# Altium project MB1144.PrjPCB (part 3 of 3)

## Sheet IDD_measurement.SchDoc: IDD_measurement
size A3; DocumentNumber: 7; Revision: C-02; SheetNumber: 7; SheetTotal: 26; Project: STM32L476G-EVAL
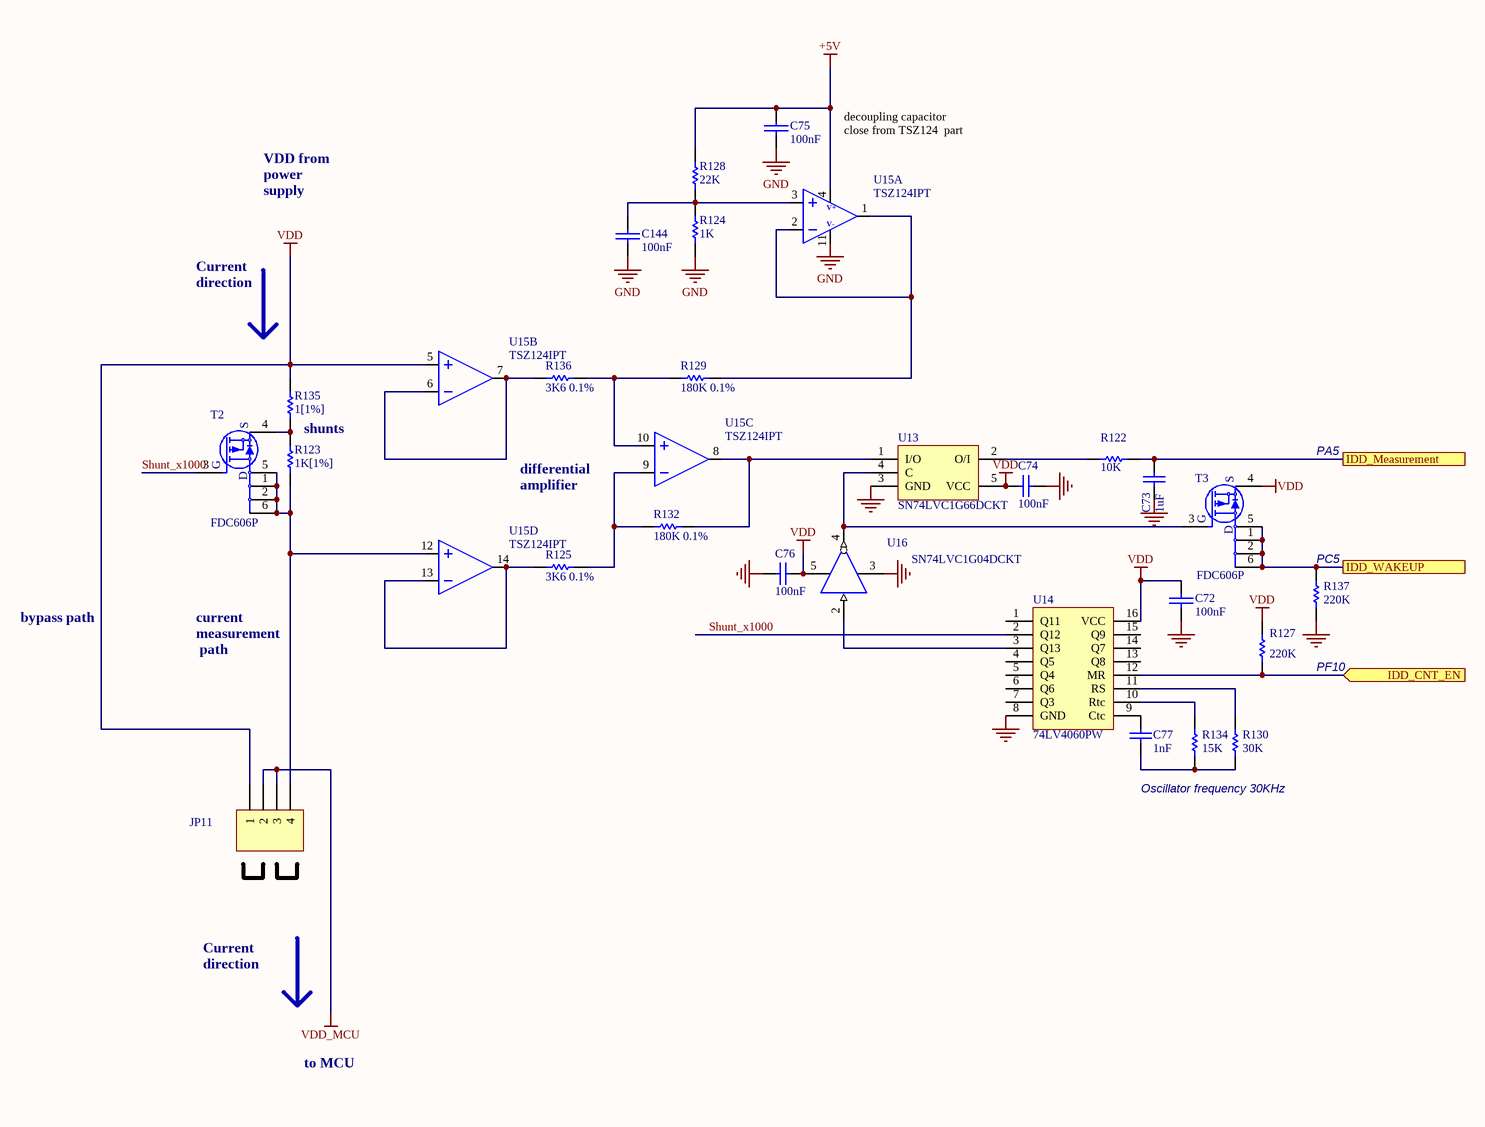
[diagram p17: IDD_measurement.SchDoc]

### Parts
C72  100nF  [0402C]
C73  1uF  [0603C]
C74  100nF  [0402C]
C75  100nF  [0402C]
C76  100nF  [0402C]
C77  1nF  [0402C]
C144  100nF  [0402C]
JP11  Header 4  [SIP4]  (value not drawn)
R122  10K  [0402R]
R123  1K[1%]  [0603R]
R124  1K  [0402R]
R125  3K6 0.1%  [0402R]
R127  220K  [0402R]
R128  22K  [0402R]
R129  180K 0.1%  [0402R]
R130  30K  [0402R]
R132  180K 0.1%  [0402R]
R134  15K  [0402R]
R135  1[1%]  [0603R]
R136  3K6 0.1%  [0402R]
R137  220K  [0402R]
T2  FDC606P  [SOT23-6]
T3  FDC606P  [SOT23-6]
U13  SN74LVC1G66DCKT  [SC70-5]
U14  74LV4060PW  [TSSOP16_0R65_5x6R4]
U15  TSZ124IPT  [TSSOP14_0R65_5X6R4]  (parts A,B,C,D of 4)
U16  SN74LVC1G04DCKT  [SC70-5]

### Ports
IDD_CNT_EN (in), IDD_Measurement, IDD_WAKEUP

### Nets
+5V: C75.1 R128.1 U15.4
GND: C72.2 C73.2 C74.1 C75.2 C76.2 C144.2 R124.2 R137.2 U13.3(GND) U14.8(GND) U15.11 U16.3(GND)
VDD: C72.1 C74.2 C76.1 JP11.1 R127.1 R135.2 T3.4(S) U13.5(VCC) U14.16(VCC) U15.5 U16.5(VCC)
VDD_MCU: JP11.2 JP11.3
Shunt_x1000: T2.3(G) U14.2(Q12)
NetC73_1: C73.1 R122.2 ; port IDD_Measurement
NetC77_1: C77.1 U14.9(Ctc)
NetC77_2: C77.2 R130.2 R134.2
NetC144_1: C144.1 R124.1 R128.2 U15.3
NetJP11_4: JP11.4 R123.1 T2.1(D) T2.2(D) T2.5(D) T2.6(D) U15.12
NetR91_1: R127.2 U14.12(MR) ; port IDD_CNT_EN
NetR122_1: R122.1 U13.2(O/I)
NetR123_2: R123.2 R135.1 T2.4(S)
NetR125_1: R125.1 U15.13 U15.14
NetR125_2: R125.2 R132.1 U15.9
NetR129_1: R129.1 R136.2 U15.10
NetR129_2: R129.2 U15.1 U15.2
NetR130_1: R130.1 U14.11(RS)
NetR132_2: R132.2 U13.1(I/O) U15.8
NetR134_1: R134.1 U14.10(Rtc)
NetR136_1: R136.1 U15.6 U15.7
NetR137_1: R137.1 T3.1(D) T3.2(D) T3.5(D) T3.6(D) ; port IDD_WAKEUP
NetT3_3: T3.3(G) U13.4(C) U16.4(1Y)
NetU14_3: U14.3(Q13) U16.2(1A)

Not connected (* = marked no-connect by the designer): U14 1(Q11) 4(Q5) 5(Q4) 6(Q6) 7(Q3) 13(Q8) 14(Q7) 15(Q9); U16 1(NC)

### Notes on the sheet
- decoupling capacitor
  close from TSZ124  part
- VDD from power supply
- Current direction
- shunts
- PA5
- differential
  amplifier
- (near R137) PC5
- bypass path
- current
  measurement
  path
- PF10
- Oscillator frequency 30KHz
- to MCU

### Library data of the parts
C72 C75 C144 = CAP: Ordered by: Subcon; ECCN_US/EU: NA
C73 = CAP: Capacitor; Value: 100nF; Ordered by: Subcon; ECCN_US/EU: NA
C74 C76 = CAP: Capacitor; Value: 100pF; Ordered by: Subcon; ECCN_US/EU: NA
C77 = Cap: Capacitor; Value: 10nF; Ordered by: Subcon; ECCN_US/EU: NA
JP11 = Header 4: Header, 4-Pin; Ordered by: Subcon
R122 R123 R125 R127-R130 R132 R134-R137 = res1: Resistor; Value: 1K; Ordered by: Subcon; ECCN_US/EU: NA
R124 = res1: Resistor; Ordered by: Subcon; ECCN_US/EU: NA
T2 T3 = STT5PF20V: Manuf_1: Fairchild; Ordered by: Subcon; ECCN_US/EU: EAR99/NEC
U13 = 74H1G66STR: Manuf_1: TI; Ordered by: Subcon; ECCN_US/EU: EAR99/NEC
U14 = M74HC4060TTR: Manuf_1: NXP; Ordered by: Subcon; ECCN_US/EU: EAR99/NEC
U15 = AOP-14PINS: Very high accuracy (5 µV) zero drift 5 V quad OpAmp; Ordered by: ST; ECCN_US/EU: EAR99/NEC; Ref St: 9177442
U16 = 74LX1G04CTR: Manuf_1: TI; Ordered by: Subcon; ECCN_US/EU: EAR99/NEC

## Sheet USB_OTG_FS.SchDoc: USB_OTG_FS
size A4; DocumentNumber: 23; Revision: C-02; SheetNumber: 23; SheetTotal: 26; Project: STM32L476G-EVAL
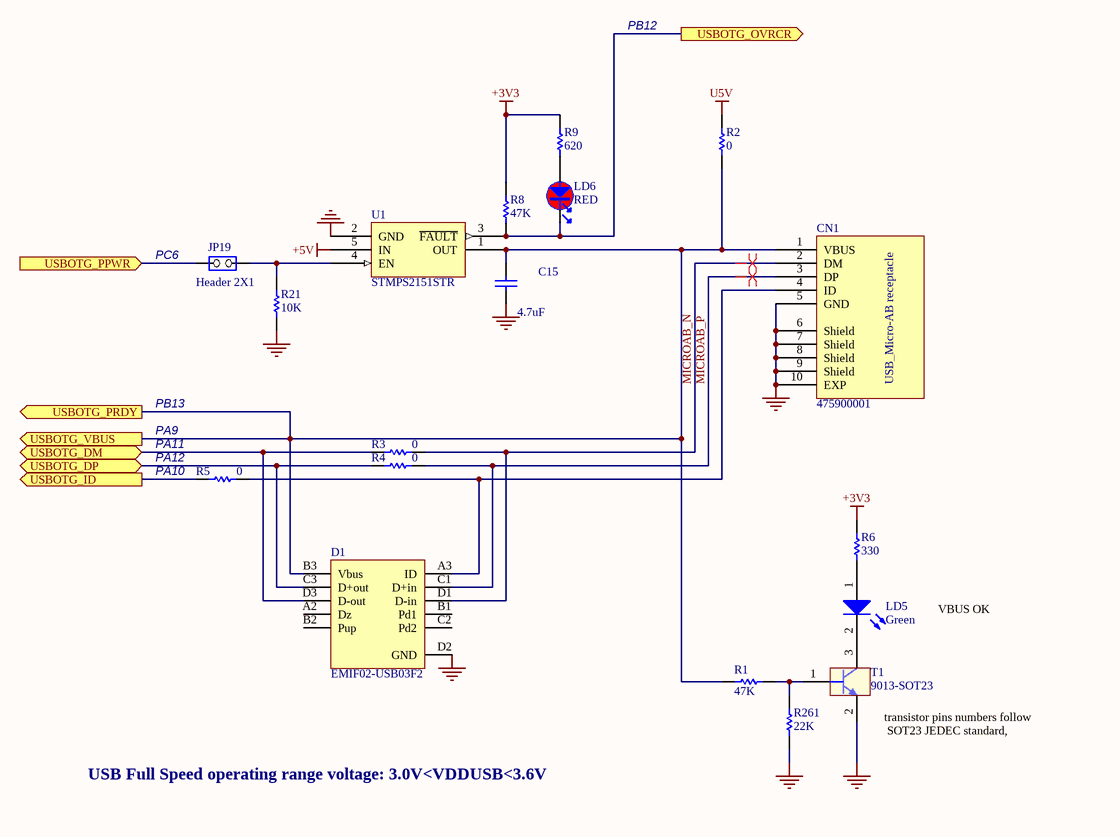
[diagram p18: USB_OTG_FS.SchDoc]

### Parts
C15  4.7uF  [0603C]
CN1  475900001  [MOLEX_47590001]
D1  EMIF02-USB03F2  [BGA11_0R5_1R57X2R07]
JP19  Header 2X1  [SIP2]
LD5  Green  [0603D]
LD6  value RED  [LED_0603_RED_H0P4]  (hidden comment: LED_red)
R1  47K  [0402R]
R2  0  [0603R]
R3  0  [0603R]
R4  0  [0603R]
R5  0  [0603R]
R6  330  [0402R]
R8  47K  [0402R]
R9  620  [0402R]
R21  10K  [0402R]
R261  22K  [0402R]
T1  9013-SOT23  [SOT-23]
U1  STMPS2151STR  [SOT23-5]

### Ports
USBOTG_DM (bidir), USBOTG_DP (bidir), USBOTG_ID (out), USBOTG_OVRCR (out), USBOTG_PPWR (in), USBOTG_PRDY (out), USBOTG_VBUS (out)

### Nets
+3V3: R6.1 R8.1 R9.1
+5V: U1.5(IN)
GND: C15.2 CN1.5(GND) CN1.6(Shield) CN1.7(Shield) CN1.8(Shield) CN1.9(Shield) CN1.10(EXP) D1.D2(GND) R21.1 R261.1 T1.2(E) U1.2(GND)
U5V: R2.1
MICROAB_N: CN1.2(DM) D1.D1(D-in) R3.1
MICROAB_P: CN1.3(DP) D1.C1(D+in) R4.1
PA11: D1.D3(D-out) R3.2 ; port USBOTG_DM
PA12: D1.C3(D+out) R4.2 ; port USBOTG_DP
NetC15_1: C15.1 CN1.1(VBUS) D1.B3(Vbus) R1.1 R2.2 U1.1(OUT) ; port USBOTG_VBUS, port USBOTG_PRDY
NetCN1_4: CN1.4(ID) D1.A3(ID) R5.1
NetCN11_6: R5.2 ; port USBOTG_ID
NetJP19_1: JP19.1(COMMON) ; port USBOTG_PPWR
NetJP19_2: JP19.2(NO) R21.2 U1.4(EN)
NetLD5_1: LD5.1(A) R6.2
NetLD5_2: LD5.2(K) T1.3(C)
NetLD6_1: LD6.1 R9.2
NetLD6_2: LD6.2 R8.2 U1.3(~{FAULT}) ; port USBOTG_OVRCR
NetR1_2: R1.2 R261.2 T1.1(B)

Not connected (* = marked no-connect by the designer): D1 A2(Dz) B1(Pd1) B2(Pup) C2(Pd2)

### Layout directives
differential pair: MICROAB_N, MICROAB_P

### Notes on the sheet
- PB12
- (near JP19) PC6
- PA9
- PB13
- (near R5) PA10
- (near R5) PA11
- (near R5) PA12
- VBUS OK
- (near T1) transistor pins numbers follow
  SOT23 JEDEC standard,
- USB Full Speed operating range voltage: 3.0V<VDDUSB<3.6V

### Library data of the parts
C15 = CAP: as C73 on sheet IDD_measurement
CN1 = 475900001: Ordered by: Subcon; ECCN_US/EU: NA; Comments: USB Micro AB receptacle
D1 = EMIF02-USB03F2: Ordered by: ST; ECCN_US/EU: EAR99/NEC; Ref St: 9179037
JP19 = JP2: Ordered by: Subcon; ECCN_US/EU: NA
LD5 = LED2: Typical RED, GREEN, YELLOW, AMBER GaAs LED; Ordered by: Subcon; ECCN_US/EU: NA
LD6 = MCD-02787: LED, Red, VF : Min=1.7V , Max=2.2V, IF : 25mA, 0603 SMD; Part_Type: Display; Part_Preference: Alternate; Manufacturer: EVERLIGHT; Manufacturer_Part_Number: 19-217/R6C-AL1M2VY/6T; Partial_Alternate_Internal_Part_Number: MCD-02401; Component_Country_Of_Origin: China; Alternate_EMS: A; ShowFields: YES; ID: 4899
R1 R6 R8 R9 R261 = res1: as R122 on sheet IDD_measurement
R2-R5 R21 = Res1: Resistor; Value: 1K; Ordered by: Subcon; ECCN_US/EU: NA
T1 = 9013-SOT23: NPN Bipolar Transistor; Manuf_1: Taitron; Manuf_Part_1: MMBT9013; Ordered by: Subcon; ECCN_US/EU: EAR99/NEC
U1 = STMPS2141STR: Ordered by: ST; ECCN_US/EU: EAR99/NEC; Ref St: 9159009

## Sheet Touch Sensing.SchDoc: Touch Sensing
size A4; DocumentNumber: 13; Revision: C-02; SheetNumber: 13; SheetTotal: 26; Project: STM32L476G-EVAL
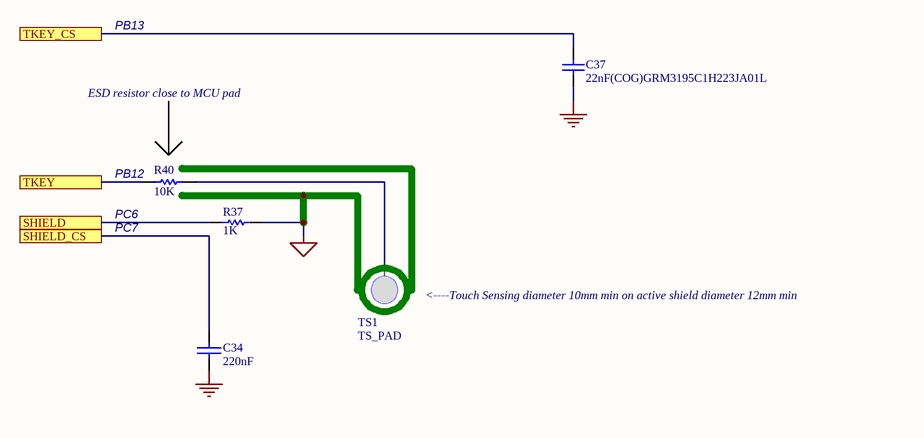
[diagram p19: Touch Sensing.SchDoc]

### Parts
C34  220nF  [0603C]
C37  22nF(COG)GRM3195C1H223JA01L  [1206C]
R37  1K  [0402R]
R40  10K  [0402R]
TS1  TS_PAD  [TS_PAD]

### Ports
SHIELD, SHIELD_CS, TKEY, TKEY_CS

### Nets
GND: C34.1 C37.1
TS_SHIELD: R37.2
NetC34_2: C34.2 ; port SHIELD_CS
NetC37_2: C37.2 ; port TKEY_CS
NetR37_1: R37.1 ; port SHIELD
NetR39_1: R40.1 ; port TKEY
NetR40_2: R40.2 TS1.1

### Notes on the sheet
- PB13
- ESD resistor close to MCU pad
- (near R40) PB12
- (near R40) PC6
- (near R40) PC7
- (near TS1) <----Touch Sensing diameter 10mm min on active shield diameter 12mm min

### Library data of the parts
C34 = CAP: Capacitor; Ordered by: Subcon; ECCN_US/EU: NA
C37 = CAP: as C74 on sheet IDD_measurement
R37 = Res1: Resistor; Ordered by: Subcon; ECCN_US/EU: NA
R40 = Res1: as R2-R5 on sheet USB_OTG_FS
TS1 = TS_PAD: Ordered by: Subcon; ECCN_US/EU: NA; Assembly: with transparent plastic cover; Comments: touch sensing button

## Sheet CAN.SchDoc: CAN
size A4; DocumentNumber: 26; Revision: C-02; SheetNumber: 26; SheetTotal: 26; Project: STM32L476G-EVAL
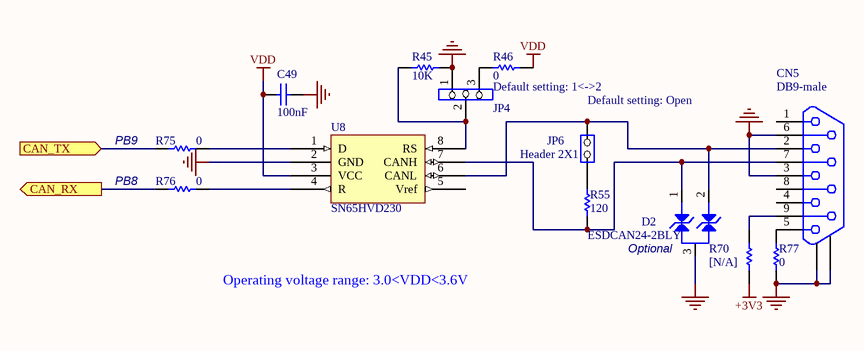
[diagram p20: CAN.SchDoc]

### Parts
C49  100nF  [0402C]
CN5  DB9-male  [DB9/M]
D2  ESDCAN24-2BLY  [SOT23-213]
JP4  Header 3X1  [SIP3]  (value not drawn)
JP6  Header 2X1  [SIP2]
R45  10K  [0402R]
R46  0  [0603R]
R55  120  [0402R]
R70  [N/A]  [0603R]
R75  0  [0603R]
R76  0  [0603R]
R77  0  [0603R]
U8  SN65HVD230  [SOIC8_1R27_4R9X6]

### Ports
CAN_RX (out), CAN_TX (in)

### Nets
+3V3: R70.1
GND: C49.1 CN5.3 CN5.6 CN5.10 CN5.11 D2.3 JP4.1 R45.2 R77.1 U8.2(GND)
VDD: C49.2 R46.2 U8.3(VCC)
NetCN5_2: CN5.2 D2.2 JP6.2(NO) U8.6(CANL)
NetCN5_5: CN5.5 R77.2
NetCN5_7: CN5.7 D2.1 R55.1 U8.7(CANH)
NetCN5_9: CN5.9 R70.2
NetCN11_8: R75.2 ; port CAN_TX
NetCN11_24: R76.1 ; port CAN_RX
NetJP4_2: JP4.2 R45.1 U8.8(RS)
NetJP4_3: JP4.3 R46.1
NetJP6_1: JP6.1(COMMON) R55.2
NetR75_1: R75.1 U8.1(D)
NetR76_2: R76.2 U8.4(R)

Not connected (* = marked no-connect by the designer): CN5 1 4 8; U8 5(Vref)

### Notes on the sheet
- Default setting: 1<->2
- (near JP6) Default setting: Open
- PB9
- PB8
- (near D2) Optional
- Operating voltage range: 3.0<VDD<3.6V

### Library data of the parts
C49 = CAP: as C34 on sheet Touch Sensing
CN5 = DB9: Ordered by: Subcon; Comments: DB9 CAN; ECCN_US/EU: NA
D2 = ESDCAN24-2BLY: Ordered by: ST; ECCN_US/EU: EAR99/NEC; Ref St: 9179002
JP4 = Jumper3: Ordered by: Subcon; ECCN_US/EU: NA
JP6 = JP2: Ordered by: Subcon; ECCN_US/EU: NA
R45 R46 R55 R77 = res1: as R122 on sheet IDD_measurement
R70 = res1: Resistor; Value: 1K; Ordered by: Subcon; ECCN_US/EU: NA; Fitted: NO
R75 R76 = Res1: as R2-R5 on sheet USB_OTG_FS
U8 = SN65HVD230D: Manuf_1: TI; Ordered by: Subcon; ECCN_US/EU: EAR99/NEC; Comments: QSPI memory

## Sheet peripherals.SchDoc: peripherals
size A4; DocumentNumber: 25; Revision: C-02; SheetNumber: 25; SheetTotal: 26; PageSetup: Record=PageOptions¦CenterHorizontal=True¦CenterVertical=True¦PrintScale=1.39¦XCorrection=1.00¦YCorrection=1.00¦PrintKind=1¦BorderSize=5000000¦LeftOffset=0¦BottomOffset=0¦Orientation=2¦PaperLength=1000¦PaperWidth=1000¦Scale=100¦PaperSource=264¦PrintQuality=600¦MediaType=1¦DitherType=10¦PaperKind=A3¦PrintScaleMode=1; Project: STM32L476G-EVAL
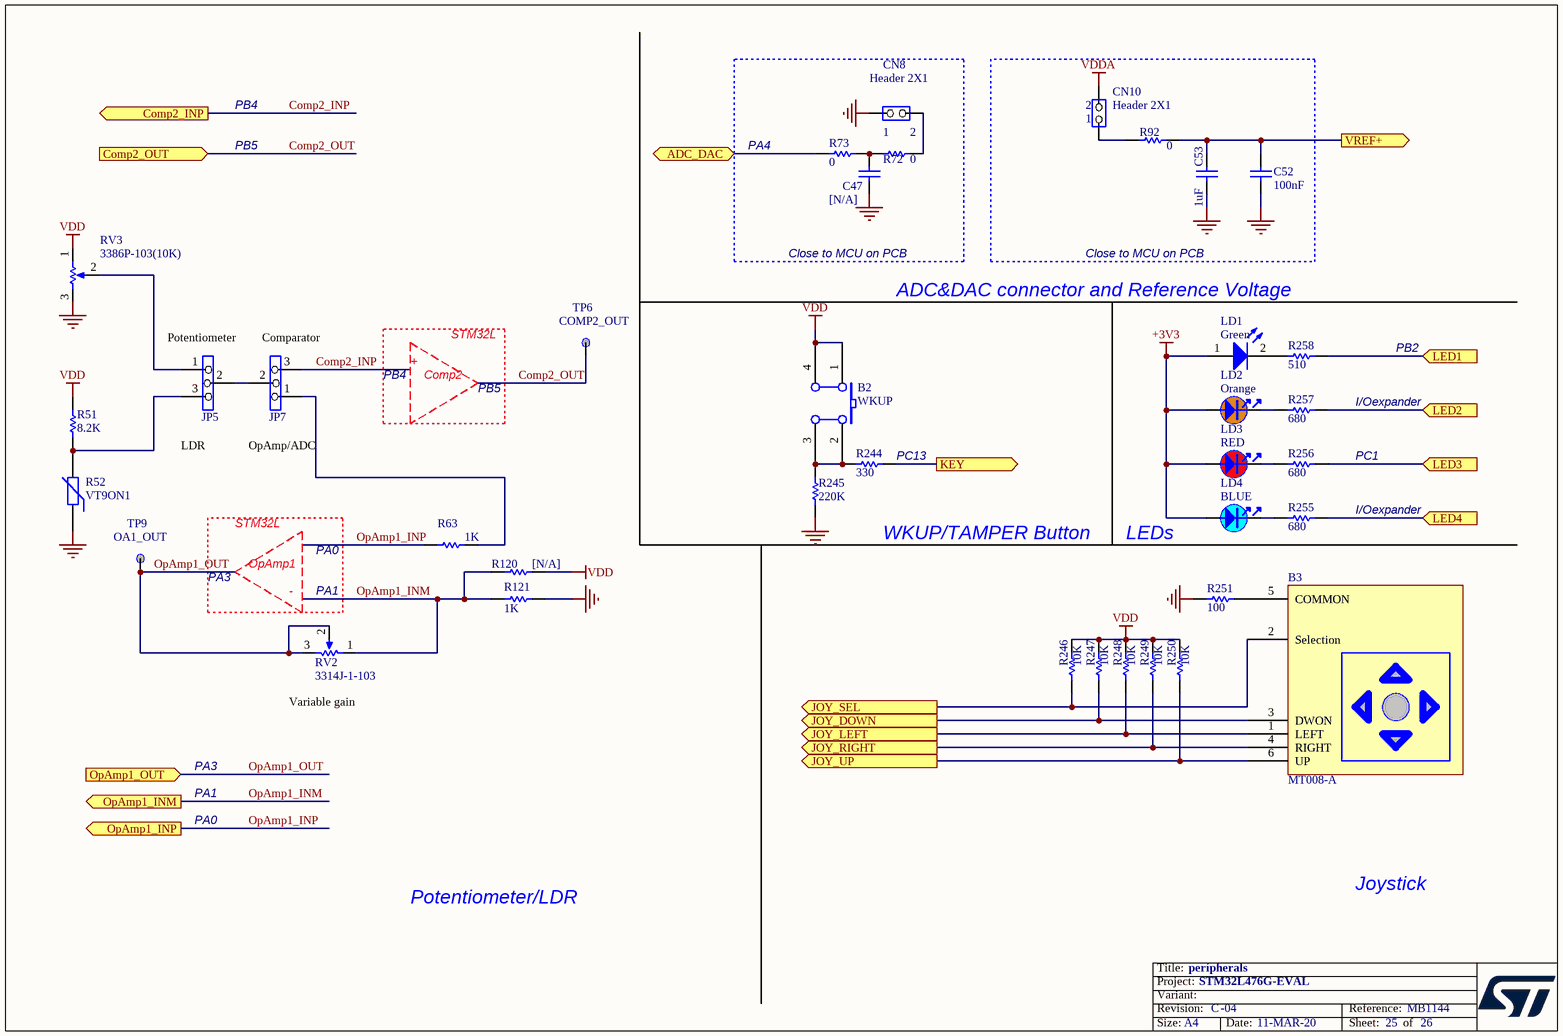
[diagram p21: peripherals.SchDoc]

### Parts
B2  WKUP  [PB10]
B3  MT008-A  [MT-008A]
C47  [N/A]  [0603C]
C52  100nF  [0402C]
C53  1uF  [0603C]
CN8  Header 2X1  [SIP2]
CN10  Header 2X1  [SIP2]
JP5  Header 3X1  [SIP3]  (value not drawn)
JP7  Header 3X1  [SIP3]  (value not drawn)
LD1  Green  [0603D]
LD2  value Orange  [LED_0603_ORANGE_H0P4]  (hidden comment: LED_orange)
LD3  value RED  [LED_0603_RED_H0P4]  (hidden comment: LED_red)
LD4  value BLUE  [LED_0603_SMD-B_BLUE_H0P4]  (hidden comment: LED_blue)
R51  8.2K  [0402R]
R52  VT9ON1  [PVT901]
R63  1K  [0402R]
R72  0  [0603R]
R73  0  [0603R]
R92  0  [0603R]
R120  [N/A]  [0603R]
R121  1K  [0402R]
R244  330  [0402R]
R245  220K  [0402R]
R246  10K  [0402R]
R247  10K  [0402R]
R248  10K  [0402R]
R249  10K  [0402R]
R250  10K  [0402R]
R251  100  [0402R]
R255  680  [0402R]
R256  680  [0402R]
R257  680  [0402R]
R258  510  [0402R]
RV2  3314J-1-103  [PTF_3314J]
RV3  3386P-103(10K)  [3386P]
TP6  TP Name: COMP2_OUT  [TP]  (hidden comment: [N/A])
TP9  TP Name: OA1_OUT  [TP]  (hidden comment: [N/A])

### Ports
ADC_DAC (bidir), Comp2_INP (out), Comp2_OUT (in), JOY_DOWN (out), JOY_LEFT (out), JOY_RIGHT (out), JOY_SEL (out), JOY_UP (out), KEY (out), LED1 (in), LED2 (in), LED3 (in), LED4 (in), OpAmp1_INM (out), OpAmp1_INP (out), OpAmp1_OUT (in), VREF+ (out)

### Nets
+3V3: LD1.1(A) LD2.1 LD3.1 LD4.1
GND: C47.1 C52.1 C53.2 CN8.1(COMMON) R52.1 R121.1 R245.2 R251.1 RV3.3(TOP)
VDD: B2.1(A0) B2.4(A1) R51.2 R120.2 R246.1 R247.2 R248.2 R249.2 R250.2 RV3.1(BOT)
VDDA: CN10.2(NO)
Comp2_INP: JP7.3 ; port Comp2_INP
Comp2_OUT: TP6.1 ; port Comp2_OUT
OpAmp1_INM: R120.1 R121.2 RV2.1(BOT) ; port OpAmp1_INM
OpAmp1_INP: R63.2 ; port OpAmp1_INP
OpAmp1_OUT: RV2.2(TAP) RV2.3(TOP) TP9.1 ; port OpAmp1_OUT
PA4: R73.1 ; port ADC_DAC
PC13: R244.2 ; port KEY
NetB2_2: B2.2(B0) B2.3(B1) R244.1 R245.1
NetB3_1: B3.1(LEFT) R248.1 ; port JOY_LEFT
NetB3_2: B3.2(Selection) R246.2 ; port JOY_SEL
NetB3_3: B3.3(DWON) R247.1 ; port JOY_DOWN
NetB3_4: B3.4(RIGHT) R249.1 ; port JOY_RIGHT
NetB3_5: B3.5(COMMON) R251.2
NetB3_6: B3.6(UP) R250.1 ; port JOY_UP
NetC47_2: C47.2 R72.1 R73.2
NetC52_2: C52.2 C53.1 R92.2 ; port VREF+
NetCN8_2: CN8.2(NO) R72.2
NetCN10_1: CN10.1(COMMON) R92.1
NetCN11_30: R256.1 ; port LED3
NetJP5_1: JP5.1 RV3.2(TAP)
NetJP5_2: JP5.2 JP7.2
NetJP5_3: JP5.3 R51.1 R52.2
NetJP7_1: JP7.1 R63.1
NetLD1_2: LD1.2(K) R258.2
NetLD2_2: LD2.2 R257.2
NetLD3_2: LD3.2 R256.2
NetLD4_2: LD4.2 R255.2
NetR54_2: R258.1 ; port LED1
NetR255_1: R255.1 ; port LED4
NetR257_1: R257.1 ; port LED2

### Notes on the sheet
- PB4
- (near CN10) 2
- PB5
- PA4
- 1
- 2
- (near CN10) 1
- Close to MCU on PCB
- ADC&DAC connector and Reference Voltage
- Potentiometer
- (near JP7) Comparator
- +
- Comp2
- STM32L
- PB2
- LDR
- OpAmp/ADC
- I/Oexpander
- (near R244) PC13
- PC1
- PA3
- OpAmp1
- PA0
- WKUP/TAMPER Button
- LEDs
- (near RV2) -
- (near RV2) PA1
- (near RV2) Variable gain
- PA1
- Potentiometer/LDR
- Joystick

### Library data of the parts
B2 = SW PUSHBUTTON: SE PUSHBUTTON; Ordered by: Subcon; Assembly: Blue; ECCN_US/EU: NA
B3 = MT-008A: Ordered by: Subcon; Assembly: with button; ECCN_US/EU: NA
C47 = cap: Capacitor; Value: 100pF; Ordered by: Subcon; ECCN_US/EU: NA; Fitted: NO
C52 = Cap: as C77 on sheet IDD_measurement
C53 = CAP: as C73 on sheet IDD_measurement
CN8 CN10 = JP2: Ordered by: Subcon; ECCN_US/EU: NA
JP5 JP7 = Jumper3: Ordered by: Subcon; ECCN_US/EU: NA
LD1 = LED2: as LD5 on sheet USB_OTG_FS
LD2 = MCD-02785: LED, Orange, VF: Min=1.7V, Max=2.2V, 25mA, 0603; Part_Type: Display; Part_Preference: Recommended; Manufacturer: EVERLIGHT; Manufacturer_Part_Number: 19-217/S2C-AM2N2VY/6T; Full_Alternate_Internal_Part_Number: MCD-00321; Component_Country_Of_Origin: China; ShowFields: YES; ID: 4897
LD3 = MCD-02787: as LD6 on sheet USB_OTG_FS
LD4 = MCD-02786: LED, Blue, VF: Min=2.5V, Max=3.1V, 10mA, 0603; Part_Type: Display; Part_Preference: Recommended; Manufacturer: EVERLIGHT; Manufacturer_Part_Number: 19-217/BHC-ZL1M2RY/6T; Full_Alternate_Internal_Part_Number: MCD-01131; Component_Country_Of_Origin: China; ShowFields: YES; ID: 4898
R51 R72 R73 R92 R244 R246-R251 R255-R258 = Res1: as R2-R5 on sheet USB_OTG_FS
R52 = Res Varistor: Varistor (Voltage-Sensitive Resistor); ECCN_US/EU: NA; Ordered by: Subcon
R63 R121 = Res1: as R37 on sheet Touch Sensing
R120 = Res1: Resistor; Value: 1K; Ordered by: Subcon; ECCN_US/EU: NA; Fitted: NO
R245 = res1: as R122 on sheet IDD_measurement
RV2 = RV: Potentiometer 10K; Ordered by: Subcon; Comments: adjustable 10K potentiometer; ECCN_US/EU: NA
RV3 = RV: Potentiometer 10K; Ordered by: Subcon; Comments: 10K potentiometer; ECCN_US/EU: NA
TP6 TP9 = TP: Ordered by: Subcon; Fitted or not fitted: NO; ECCN_US/EU: NA; Fitted: NO

## Sheet Power.SchDoc: Power
size A4; DocumentNumber: 8; Revision: C-02; SheetNumber: 8; SheetTotal: 26; Project: STM32L476G-EVAL
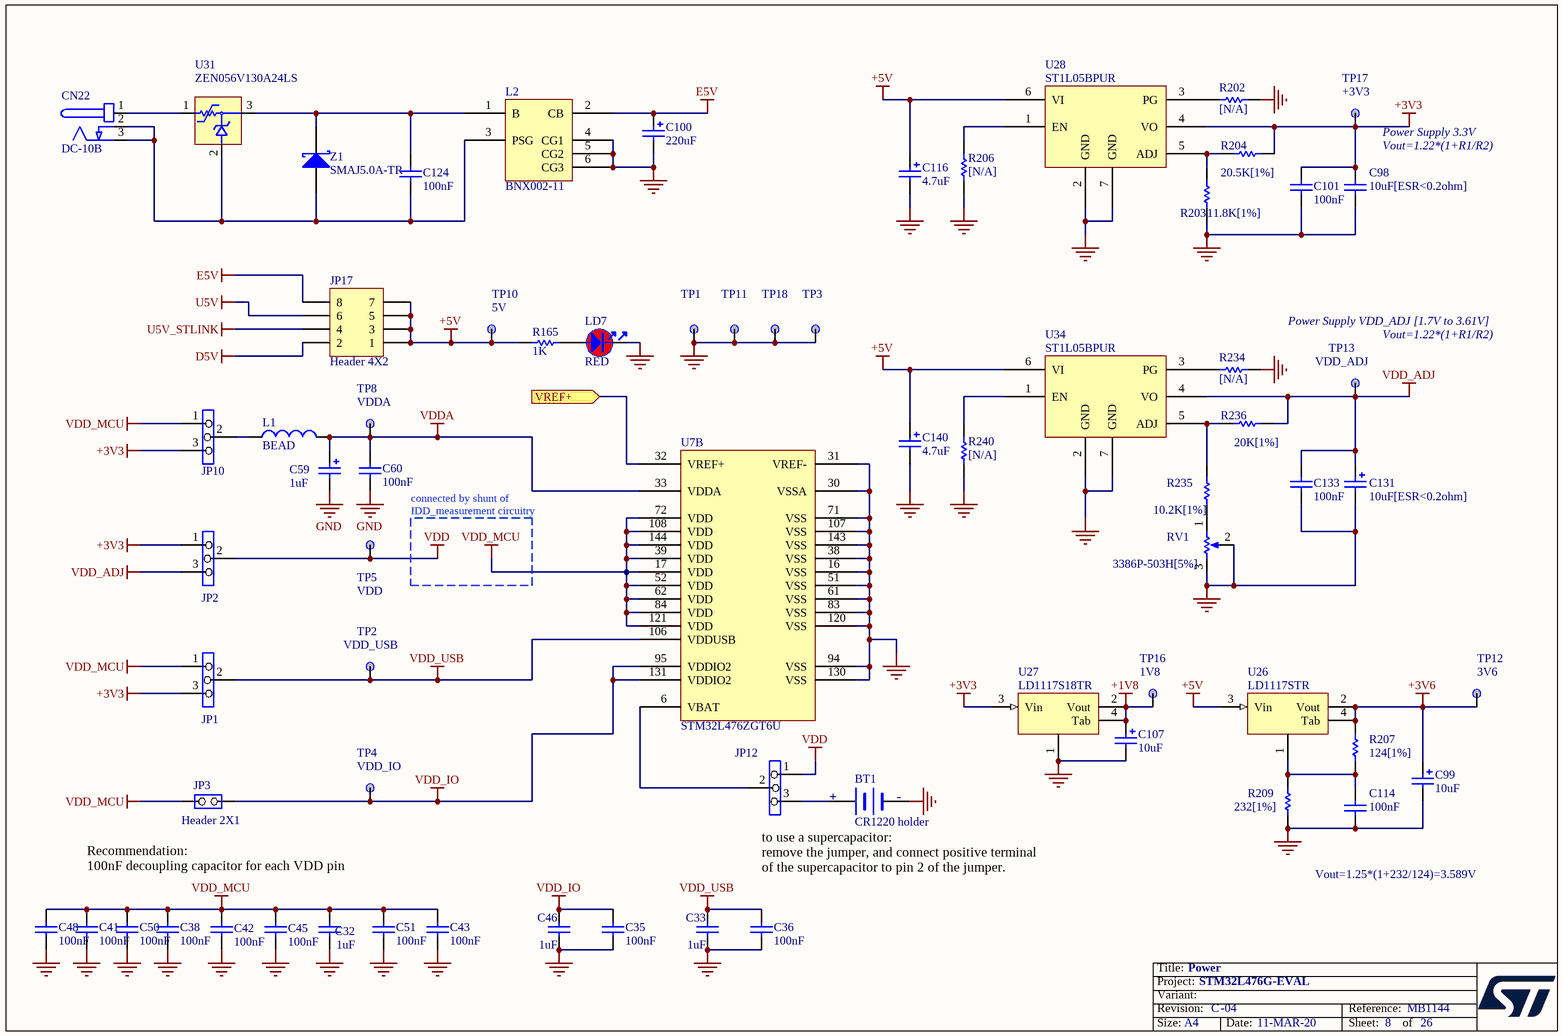
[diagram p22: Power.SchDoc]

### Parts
BT1  CR1220 holder  [BAT_2SM_CR1220]
C32  1uF  [0603C]
C33  1uF  [0603C]
C35  100nF  [0402C]
C36  100nF  [0402C]
C38  100nF  [0402C]
C41  100nF  [0402C]
C42  100nF  [0402C]
C43  100nF  [0402C]
C45  100nF  [0402C]
C46  1uF  [0603C]
C48  100nF  [0402C]
C50  100nF  [0402C]
C51  100nF  [0402C]
C59  1uF  [TAN-A]
C60  100nF  [0402C]
C98  10uF[ESR<0.2ohm]  [0805C]
C99  10uF  [TAN-A]
C100  220uF  [c310m-6]
C101  100nF  [0402C]
C107  10uF  [TAN-A]
C114  100nF  [0402C]
C116  4.7uF  [TAN-A]
C124  100nF  [0402C]
C131  10uF[ESR<0.2ohm]  [0805C]
C133  100nF  [0402C]
C140  4.7uF  [TAN-A]
CN22  DC-10B  [PWR_JACK_DC10]
JP1  Header 3X1  [SIP3]  (value not drawn)
JP2  Header 3X1  [SIP3]  (value not drawn)
JP3  Header 2X1  [SIP2]
JP10  Header 3X1  [SIP3]  (value not drawn)
JP12  Header 3X1  [SIP3]  (value not drawn)
JP17  Header 4X2  [HDR_2X4_2R54]
L1  BEAD  [0603L]
L2  value BNX002-11  [FIL_MURATA_BNX002-01]  (hidden comment: BNX002-01)
LD7  value RED  [LED_0603_RED_H0P4]  (hidden comment: LED_red)
R165  1K  [0402R]
R202  [N/A]  [0603R]
R203  11.8K[1%]  [0603R]
R204  20.5K[1%]  [0603R]
R206  [N/A]  [0603R]
R207  124[1%]  [0603R]
R209  232[1%]  [0603R]
R234  [N/A]  [0603R]
R235  10.2K[1%]  [0603R]
R236  20K[1%]  [0603R]
R240  [N/A]  [0603R]
RV1  3386P-503H[5%]  [3386P]
TP1  [N/A]  [TP]  (value not drawn)
TP2  TP Name: VDD_USB  [TP]  (hidden comment: [N/A])
TP3  [N/A]  [TP]  (value not drawn)
TP4  TP Name: VDD_IO  [TP]  (hidden comment: [N/A])
TP5  TP Name: VDD  [TP]  (hidden comment: [N/A])
TP8  TP Name: VDDA  [TP]  (hidden comment: [N/A])
TP10  TP Name: 5V  [TP]  (hidden comment: [N/A])
TP11  [N/A]  [TP]  (value not drawn)
TP12  TP Name: 3V6  [TP]  (hidden comment: [N/A])
TP13  TP Name: VDD_ADJ  [TP]  (hidden comment: [N/A])
TP16  TP Name: 1V8  [TP]  (hidden comment: [N/A])
TP17  TP Name: +3V3  [TP]  (hidden comment: [N/A])
TP18  [N/A]  [TP]  (value not drawn)
U7  STM32L476ZGT6U  [TQFP144_0R5_22X22_SOCKET]  (part B of 3)
U26  LD1117STR  [SOT-223]
U27  LD1117S18TR  [SOT-223]
U28  ST1L05BPUR  [DFN6_0R95_3X3]
U31  ZEN056V130A24LS  [TYCO_ZEN056V130A24LS]
U34  ST1L05BPUR  [DFN6_0R95_3X3]
Z1  SMAJ5.0A-TR  [sma]

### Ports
VREF+ (in)

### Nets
+1V8: C107.1 TP16.1 U27.2(Vout) U27.4(Tab)
+3V3: C98.1 C101.1 JP1.3 JP2.1 JP10.3 R204.1 TP17.1 U27.3(Vin) U28.4(VO)
+3V6: C99.1 R207.2 TP12.1 U26.2(Vout) U26.4(Tab)
+5V: C116.1 C140.1 JP17.1 JP17.3 JP17.5 JP17.7 R165.2 TP10.1 U26.3(Vin) U28.6(VI) U34.6(VI)
D5V: JP17.2
E5V: C100.1 JP17.8 L2.2(CB)
GND: BT1.2(-) C32.2 C33.2 C35.1 C36.1 C38.1 C41.1 C42.2 C43.1 C45.2 C46.2 C48.1 C50.1 C51.1 C59.2 C60.1 C98.2 C99.2 C100.2 C101.2 C107.2 C114.2 C116.2 C131.2 C133.2 C140.2 L2.4(CG1) L2.5(CG2) L2.6(CG3) LD7.2 R202.1 R203.2 R206.2 R209.1 R234.1 R240.2 RV1.2(TAP) RV1.3(TOP) TP1.1 TP3.1 TP11.1 TP18.1 U7.16(VSS) U7.30(VSSA) U7.31(VREF-) U7.38(VSS) U7.51(VSS) U7.61(VSS) U7.71(VSS) U7.83(VSS) U7.94(VSS) U7.107(VSS) U7.120(VSS) U7.130(VSS) U7.143(VSS) U27.1 U28.2(GND) U28.7(GND) U34.2(GND) U34.7(GND)
U5V: JP17.6
U5V_STLINK: JP17.4
VDD: JP2.2 JP12.1 TP5.1
VDD_ADJ: C131.1 C133.1 JP2.3 R236.1 TP13.1 U34.4(VO)
VDD_IO: C35.2 C46.1 JP3.2(NO) TP4.1 U7.95(VDDIO2) U7.131(VDDIO2)
VDD_MCU: C32.1 C38.2 C41.2 C42.1 C43.2 C45.1 C48.2 C50.2 C51.2 JP1.1 JP3.1(COMMON) JP10.1 U7.17(VDD) U7.39(VDD) U7.52(VDD) U7.62(VDD) U7.72(VDD) U7.84(VDD) U7.108(VDD) U7.121(VDD) U7.144(VDD)
VDD_USB: C33.1 C36.2 JP1.2 TP2.1 U7.106(VDDUSB)
VDDA: C59.1 C60.2 L1.2 TP8.1 U7.33(VDDA)
NetBT1_1: BT1.1(+) JP12.3
NetC52_2: U7.32(VREF+) ; port VREF+
NetC114_1: C114.1 R207.1 R209.2 U26.1
NetC124_1: C124.1 L2.1(B) U31.3 Z1.2(K)
NetC124_2: C124.2 CN22.2(GND) CN22.3(GND) L2.3(PSG) U31.2 Z1.1(A)
NetCN22_1: CN22.1(+) U31.1
NetJP10_2: JP10.2 L1.1
NetJP12_2: JP12.2 U7.6(VBAT)
NetLD7_1: LD7.1 R165.1
NetR202_2: R202.2 U28.3(PG)
NetR203_1: R203.1 R204.2 U28.5(ADJ)
NetR206_1: R206.1 U28.1(EN)
NetR234_2: R234.2 U34.3(PG)
NetR235_1: R235.1 R236.2 U34.5(ADJ)
NetR235_2: R235.2 RV1.1(BOT)
NetR240_1: R240.1 U34.1(EN)

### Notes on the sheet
- Power Supply 3.3V
- Vout=1.22*(1+R1/R2)
- Power Supply VDD_ADJ [1.7V to 3.61V]
- (near TP13) Vout=1.22*(1+R1/R2)
- connected by shunt of
  IDD_measurement circuitry
- (near BT1) +
- (near BT1) -
- Recommendation:
  100nF decoupling capacitor for each VDD pin
- to use a supercapacitor:
  remove the jumper, and connect positive terminal
  of the supercapacitor to pin 2 of the jumper.
- Vout=1.25*(1+232/124)=3.589V

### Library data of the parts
BT1 = BATTERY: Ordered by: Subcon; Assembly: with battery; ECCN_US/EU: NA
C32 C33 C46 = CAP: as C73 on sheet IDD_measurement
C35 C36 C60 C98 C101 C114 C133 = Cap: as C77 on sheet IDD_measurement
C38 C41-C43 C45 C48 C50 C51 = CAP: as C34 on sheet Touch Sensing
C59 C131 = Cap Pol1: Polarized Capacitor (Radial); Value: 10uF; Ordered by: Subcon; ECCN_US/EU: NA
C99 = Cap Pol1: Polarized Capacitor (Radial); ECCN_US/EU: NA; Ordered by: Subcon
C100 = Cap Pol1: Polarized Capacitor (Radial); Value: 47uF; Ordered by: Subcon; ECCN_US/EU: NA
C107 = Cap Pol1: Polarized Capacitor (Radial); Ordered by: Subcon; ECCN_US/EU: NA
C116 C140 = Cap Pol1: Polarized Capacitor (Radial); Value: 100pF; Ordered by: Subcon; ECCN_US/EU: NA
C124 = CAP: as C74 on sheet IDD_measurement
CN22 = PJ202A: Ordered by: Subcon; Comments: power jack; ECCN_US/EU: NA
JP1 JP2 JP10 JP12 = Jumper3: Ordered by: Subcon; ECCN_US/EU: NA
JP3 = JP2: Ordered by: Subcon; ECCN_US/EU: NA
JP17 = Header 4X2: Header, 4-Pin, Dual row; Ordered by: Subcon; ECCN_US/EU: NA
L1 = Inductor: Value: 100uH; Ordered by: Subcon; ECCN_US/EU: NA
L2 = MCD-02155: Inductor, DC Power EMI line filter, 40dB min (1MHz - 1GHz) insertion loss, 10A; Part_Preference: Recommended; Manufacturer: MURATA
LD7 = MCD-02787: as LD6 on sheet USB_OTG_FS
R165 = res1: as R124 on sheet IDD_measurement
R202 R206 R234 R240 = res1: as R70 on sheet CAN
R203 R204 R235 R236 = Res1: as R2-R5 on sheet USB_OTG_FS
R207 R209 = Res1: Resistor; Value: 1K; ECCN_US/EU: NA; Ordered by: Subcon
RV1 = RV: Potentiometer 50K; Ordered by: Subcon; Comments: 50K potentiometer; ECCN_US/EU: NA
TP1 TP3 TP11 TP18 = TP: TP Name: GND; Ordered by: Subcon; Fitted or not fitted: NO; ECCN_US/EU: NA; Fitted: NO
TP2 TP4 TP5 TP8 TP10 TP12 TP13 TP16 TP17 = TP: as TP6 on sheet peripherals
U7 = STM32L476_TQFP144: Manuf_Part_1: STM32L476ZGT6U cut1.3; Ordered by: ST; ECCN_US/EU: 3A991A2/NEC; Assembly: MCU; Ref St: 9175195
U26 = LD1117: Ordered by: ST; ECCN_US/EU: EAR99/NEC; Ref St: 9176138
U27 = LD1117: Ordered by: ST; ECCN_US/EU: EAR99/NEC; Ref St: 9176180
U28 U34 = ST1L05: Ordered by: ST; ECCN_US/EU: EAR99/NEC; Ref St: 9176239
U31 = ZEN056V130A24LS: Manuf_1: TYCO; Ordered by: Subcon; ECCN_US/EU: EAR99/NEC
Z1 = D Schottky: Schottky Diode; Code - JEDEC: DO-214-AA; Ordered by: ST; ECCN_US/EU: EAR99/NEC; Ref St: 9151107

## Sheet Audio.SchDoc: Audio
size A4; DocumentNumber: 18; Revision: C-02; SheetNumber: 18; SheetTotal: 26; Project: STM32L476G-EVAL
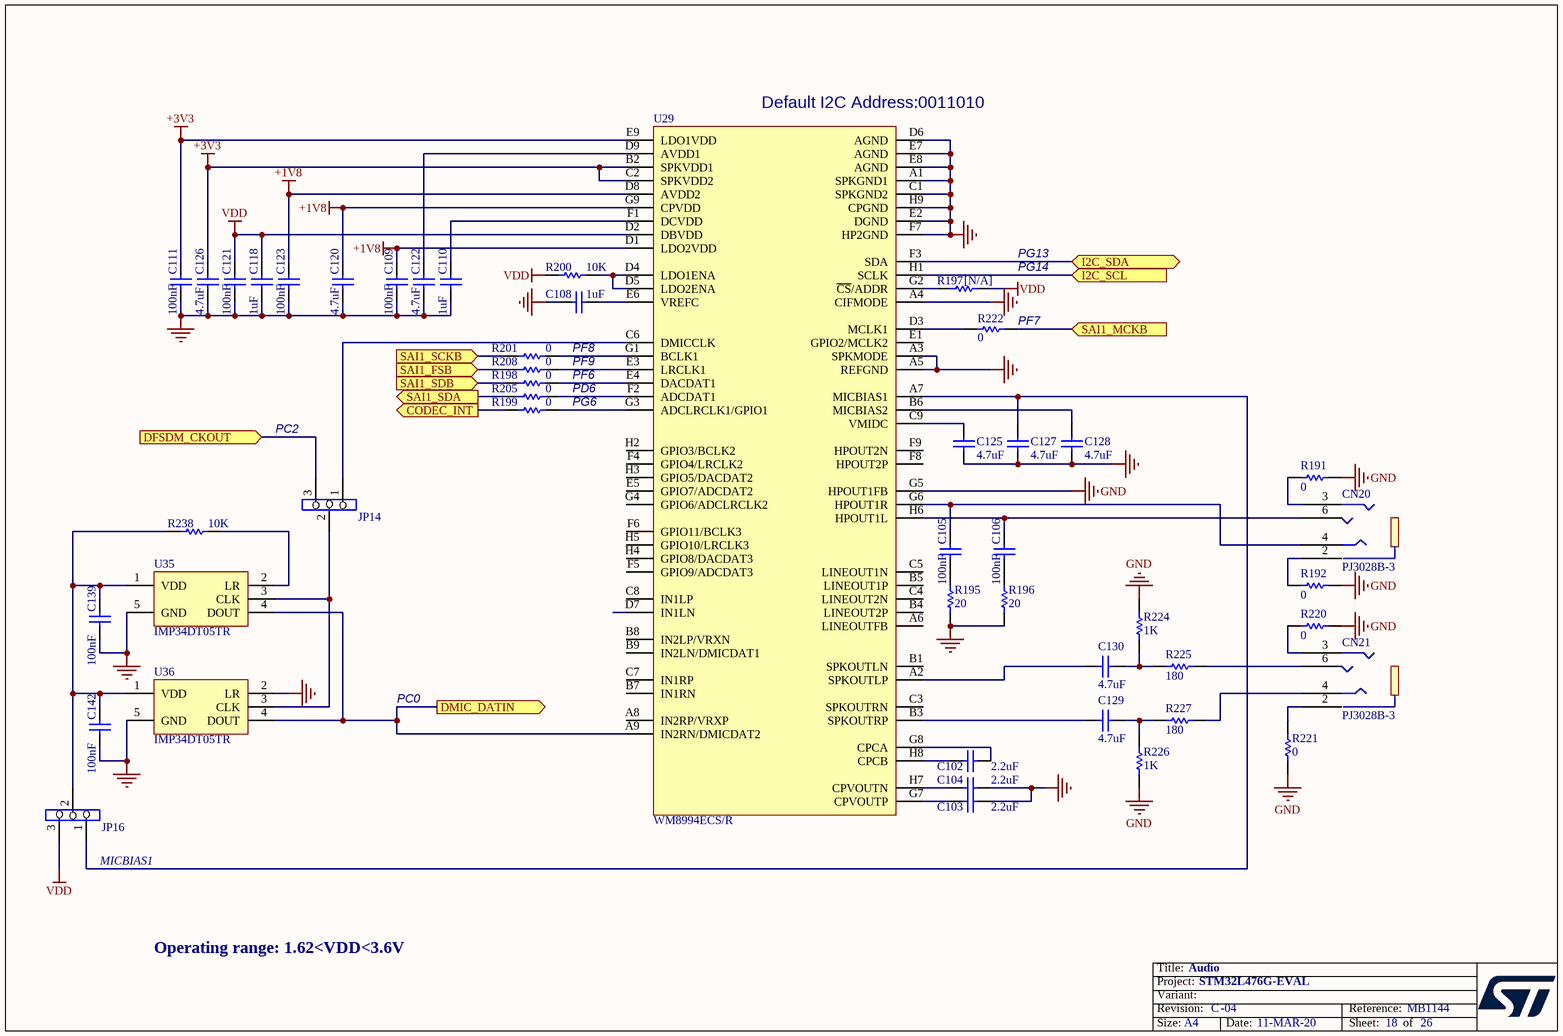
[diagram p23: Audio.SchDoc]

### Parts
C102  value 2.2uF  [C0603]  (hidden comment: Capacitor)
C103  value 2.2uF  [C0603]  (hidden comment: Capacitor)
C104  value 2.2uF  [C0603]  (hidden comment: Capacitor)
C105  100nF  [0402C]
C106  100nF  [0402C]
C108  1uF  [0603C]
C109  100nF  [0402C]
C110  1uF  [0603C]
C111  100nF  [0402C]
C118  1uF  [0603C]
C120  4.7uF  [0603C]
C121  100nF  [0402C]
C122  4.7uF  [0603C]
C123  100nF  [0402C]
C125  4.7uF  [0603C]
C126  4.7uF  [0603C]
C127  4.7uF  [0603C]
C128  4.7uF  [0603C]
C129  4.7uF  [0603C]
C130  4.7uF  [0603C]
C139  100nF  [0402C]
C142  100nF  [0402C]
CN20  PJ3028B-3  [PJ3028B]
CN21  PJ3028B-3  [PJ3028B]
JP14  Header 3X1  [SIP3]  (value not drawn)
JP16  Header 3X1  [SIP3]  (value not drawn)
R191  0  [0603R]
R192  0  [0603R]
R195  20  [0402R]
R196  20  [0402R]
R197  [N/A]  [0603R]
R198  0  [0603R]
R199  0  [0603R]
R200  10K  [0402R]
R201  0  [0603R]
R205  0  [0603R]
R208  0  [0603R]
R220  0  [0603R]
R221  0  [0603R]
R222  0  [0603R]
R224  1K  [0402R]
R225  180  [0402R]
R226  1K  [0402R]
R227  180  [0402R]
R238  10K  [0402R]
U29  WM8994ECS/R  [BGA72_0R5_4R5X4]
U35  IMP34DT05TR  [MIC_HCLGA_3X4X1_4LD]
U36  IMP34DT05TR  [MIC_HCLGA_3X4X1_4LD]

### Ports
CODEC_INT (out), DFSDM_CKOUT (in), DMIC_DATIN (out), I2C_SCL (in), I2C_SDA (bidir), SAI1_FSB (in), SAI1_MCKB (in), SAI1_SCKB (in), SAI1_SDA (out), SAI1_SDB (in)

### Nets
+1V8: C109.1 C120.1 C123.1 U29.D1(LDO2VDD) U29.D8(AVDD2) U29.G9(CPVDD)
+3V3: C111.1 C126.1 U29.B2(SPKVDD1) U29.C2(SPKVDD2) U29.E9(LDO1VDD)
GND: C103.2 C104.2 C108.2 C109.2 C110.2 C111.2 C118.2 C120.2 C121.2 C122.2 C123.2 C125.1 C126.2 C127.1 C128.1 C139.2 C142.2 R191.2 R192.1 R195.2 R196.2 R220.2 R221.2 R224.1 R226.1 U29.A1(SPKGND1) U29.A3(SPKMODE) U29.A4(CIFMODE) U29.A5(REFGND) U29.C1(SPKGND2) U29.D6(AGND) U29.E2(DGND) U29.E7(AGND) U29.E8(AGND) U29.F7(HP2GND) U29.G5(HPOUT1FB) U29.H9(CPGND) U35.5(GND) U36.2(LR) U36.5(GND)
VDD: C118.1 C121.1 JP16.3 R197.1 R200.2 U29.D2(DBVDD)
I2C_SCL: U29.H1(SCLK) ; port I2C_SCL
I2C_SDA: U29.F3(SDA) ; port I2C_SDA
NetC102_1: C102.1 U29.H8(CPCB)
NetC102_2: C102.2 U29.G8(CPCA)
NetC103_1: C103.1 U29.G7(CPVOUTP)
NetC104_1: C104.1 U29.H7(CPVOUTN)
NetC105_1: C105.1 CN20.4 U29.G6(HPOUT1R)
NetC105_2: C105.2 R195.1
NetC106_1: C106.1 CN20.6 U29.H6(HPOUT1L)
NetC106_2: C106.2 R196.1
NetC108_1: C108.1 U29.E6(VREFC)
NetC110_1: C110.1 U29.F1(DCVDD)
NetC122_1: C122.1 U29.D9(AVDD1)
NetC125_2: C125.2 U29.C9(VMIDC)
NetC127_2: C127.2 JP16.1 U29.A7(MICBIAS1)
NetC128_2: C128.2 U29.B6(MICBIAS2)
NetC129_1: C129.1 R226.2 R227.2
NetC129_2: C129.2 U29.B3(SPKOUTRP)
NetC130_1: C130.1 R224.2 R225.1
NetC130_2: C130.2 U29.A2(SPKOUTLP)
NetC139_1: C139.1 C142.1 JP16.2 R238.2 U35.1(VDD) U36.1(VDD)
NetCN11_28: JP14.3 ; port DFSDM_CKOUT
NetCN11_32: U29.A9(IN2RN/DMICDAT2) U35.4(DOUT) U36.4(DOUT) ; port DMIC_DATIN
NetCN20_2: CN20.2 R192.2
NetCN20_3: CN20.3 R191.1
NetCN21_2: CN21.2 R221.1
NetCN21_3: CN21.3 R220.1
NetCN21_4: CN21.4 R227.1
NetCN21_6: CN21.6 R225.2
NetJP14_1: JP14.1 U29.C6(DMICCLK)
NetJP14_2: JP14.2 U35.3(CLK) U36.3(CLK)
NetR35_1: R199.2 ; port CODEC_INT
NetR53_2: R205.2 ; port SAI1_SDA
NetR89_1: R201.2 ; port SAI1_SCKB
NetR90_1: R208.2 ; port SAI1_FSB
NetR105_1: R198.2 ; port SAI1_SDB
NetR106_1: R222.1 ; port SAI1_MCKB
NetR197_2: R197.2 U29.G2(~{CS}/ADDR)
NetR198_1: R198.1 U29.E4(DACDAT1)
NetR199_1: R199.1 U29.G3(ADCLRCLK1/GPIO1)
NetR200_1: R200.1 U29.D4(LDO1ENA) U29.D5(LDO2ENA)
NetR201_1: R201.1 U29.G1(BCLK1)
NetR205_1: R205.1 U29.F2(ADCDAT1)
NetR208_1: R208.1 U29.E3(LRCLK1)
NetR222_2: R222.2 U29.D3(MCLK1)
NetR238_1: R238.1 U35.2(LR)

Not connected (* = marked no-connect by the designer): U29 A6(LINEOUTFB) A8(IN2RP/VRXP) B1(SPKOUTLN) B4(LINEOUT2P) B5(LINEOUT1P) B7(IN1RN) B8(IN2LP/VRXN) B9(IN2LN/DMICDAT1) C3(SPKOUTRN) C4(LINEOUT2N) C5(LINEOUT1N) C7(IN1RP) C8(IN1LP) D7(IN1LN) E1(GPIO2/MCLK2) E5(GPIO7/ADCDAT2) F4(GPIO4/LRCLK2) F5(GPIO9/ADCDAT3) F6(GPIO11/BCLK3) F8(HPOUT2P) F9(HPOUT2N) G4(GPIO6/ADCLRCLK2) H2(GPIO3/BCLK2) H3(GPIO5/DACDAT2) H4(GPIO8/DACDAT3) H5(GPIO10/LRCLK3)

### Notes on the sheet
- (near U29) Default I2C Address:0011010
- PG13
- PG14
- PF8
- PF9
- PF6
- (near R222) PF7
- PC2
- PD6
- PG6
- PC0
- (near JP16) MICBIAS1
- Operating range: 1.62<VDD<3.6V

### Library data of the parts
C102-C104 = MCD-02468: Capacitor, 2.2uF, +/-10%, 10V, X5R, 0603, T=0.8mm; Part_Preference: Recommended; Manufacturer: TDK; Manufacturer_Part_Number: C1608X5R1C225K080AB; Order_Code_RS: 788-2900
C105 C106 C109 C111 C120-C123 C125-C130 C139 C142 = Cap: as C77 on sheet IDD_measurement
C108 C110 C118 = CAP: as C73 on sheet IDD_measurement
CN20 CN21 = PJ3028B-3: ECCN_US/EU: NA; Ordered by: Subcon; Comments: Audio jack
JP14 JP16 = Jumper3: Ordered by: Subcon; ECCN_US/EU: NA
R191 R192 R195 R196 R198-R201 R205 R208 R220-R222 R225 R227 R238 = Res1: as R2-R5 on sheet USB_OTG_FS
R197 = Res1: as R120 on sheet peripherals
R224 R226 = Res1: as R37 on sheet Touch Sensing
U29 = WM8994ECS/R: Manuf_1: Wolfson; Ordered by: Subcon; ECCN_US/EU: EAR99/NEC
U35 U36 = MCD-01715: MEMS audio sensor omnidirectional digital microphone for industrial applications; BMS_Part_Number: 9177995; Part_Type: IC; Part_Preference: Recommended; Manufacturer: STMICROELECTRONICS; Manufacturer_HQ_COO: EU; Component_Country_Of_Origin: Philippines

## Sheet LCD_TFT.SchDoc: LCD_TFT
size A3; DocumentNumber: 11; Revision: C-02; SheetNumber: 11; SheetTotal: 26; PageSetup: Record=PageOptions¦CenterHorizontal=True¦CenterVertical=True¦PrintScale=1.01¦XCorrection=1.00¦YCorrection=1.00¦PrintKind=1¦BorderSize=5000000¦LeftOffset=0¦BottomOffset=0¦Orientation=2¦PaperLength=1000¦PaperWidth=1000¦Scale=100¦PaperSource=15¦PrintQuality=600¦MediaType=1¦DitherType=10¦PaperKind=A3¦PrintScaleMode=1; Project: STM32L476G-EVAL
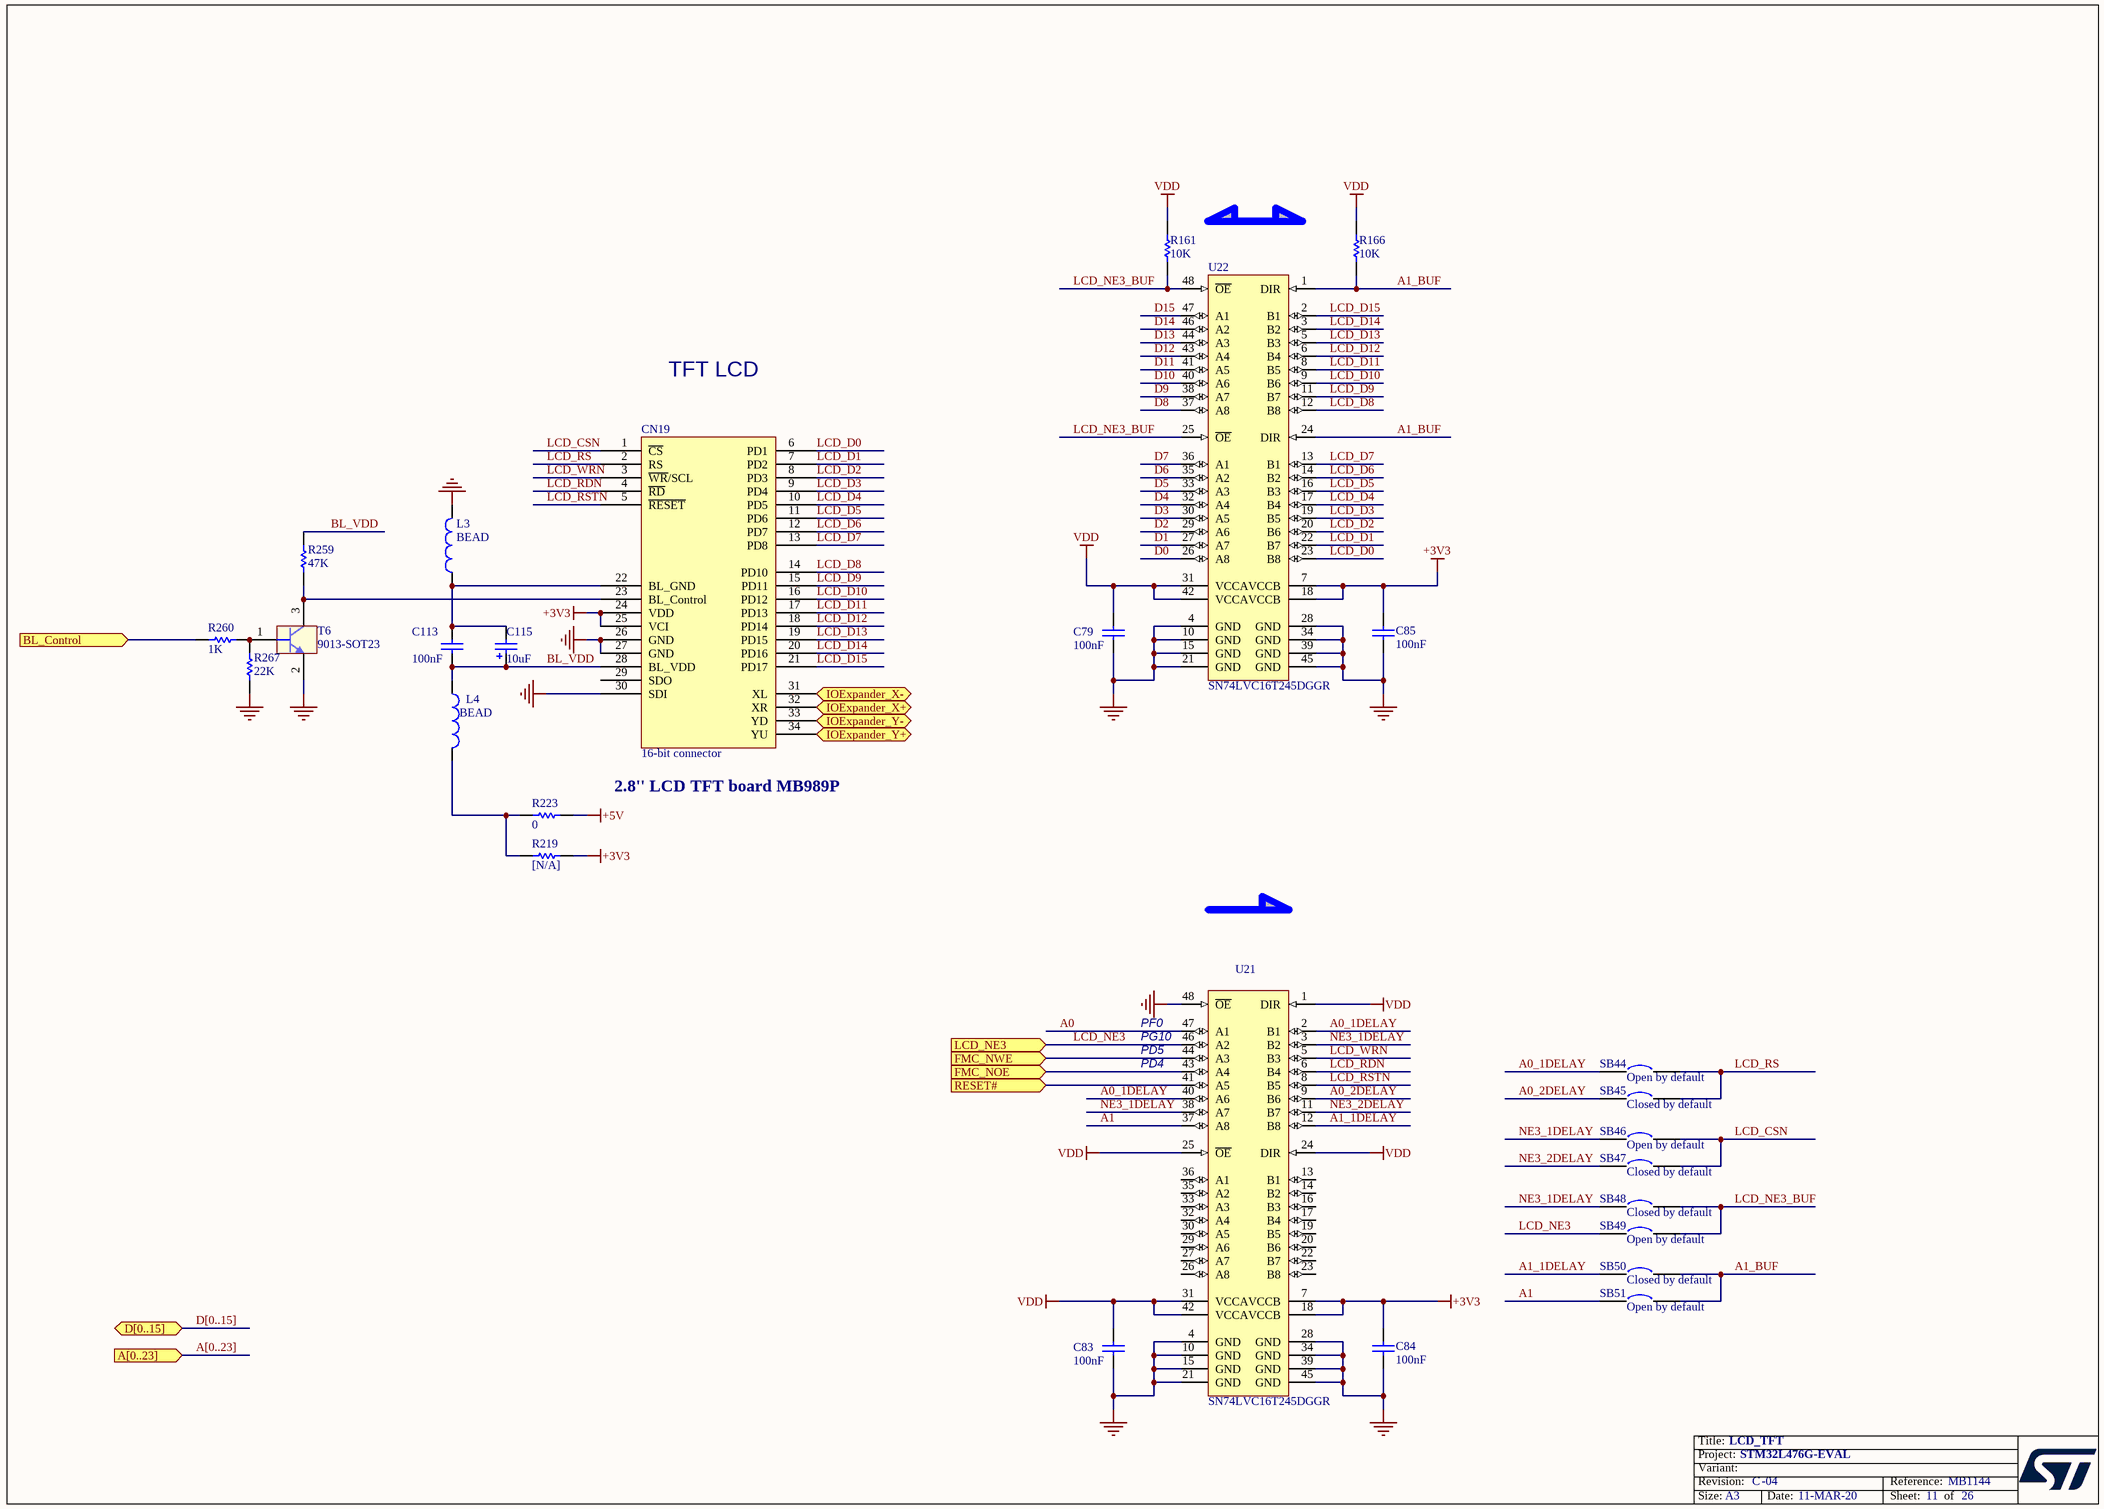
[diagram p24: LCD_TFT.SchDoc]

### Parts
C79  100nF  [0402C]
C83  100nF  [0402C]
C84  100nF  [0402C]
C85  100nF  [0402C]
C113  100nF  [0402C]
C115  10uF  [TAN-A]
CN19  16-bit connector  [HDR_2X17_2R54]
L3  BEAD  [0603L]
L4  BEAD  [0603L]
R161  10K  [0402R]
R166  10K  [0402R]
R219  [N/A]  [0603R]
R223  0  [0603R]
R259  47K  [0402R]
R260  1K  [0402R]
R267  22K  [0402R]
SB44  Open by default  [SB_0603]
SB45  Closed by default  [SB_0603]
SB46  Open by default  [SB_0603]
SB47  Closed by default  [SB_0603]
SB48  Closed by default  [SB_0603]
SB49  Open by default  [SB_0603]
SB50  Closed by default  [SB_0603]
SB51  Open by default  [SB_0603]
T6  9013-SOT23  [SOT-23]
U21  SN74LVC16T245DGGR  [TSSOP48_0R5_12R5X8R1]
U22  SN74LVC16T245DGGR  [TSSOP48_0R5_12R5X8R1]

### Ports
A[0..23] (in), BL_Control (in), D[0..15] (bidir), FMC_NOE (in), FMC_NWE (in), IOExpander_X+ (bidir), IOExpander_X- (bidir), IOExpander_Y+ (bidir), IOExpander_Y- (bidir), LCD_NE3 (in), RESET# (in)

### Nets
+3V3: C84.1 C85.1 CN19.24(VDD) CN19.25(VCI) R219.1 U21.7(VCCB) U21.18(VCCB) U22.7(VCCB) U22.18(VCCB)
+5V: R223.1
GND: C79.2 C83.2 C84.2 C85.2 CN19.26(GND) CN19.27(GND) CN19.30(SDI) L3.2 R267.2 T6.2(E) U21.4(GND) U21.10(GND) U21.15(GND) U21.21(GND) U21.28(GND) U21.34(GND) U21.39(GND) U21.45(GND) U21.48(~{OE}) U22.4(GND) U22.10(GND) U22.15(GND) U22.21(GND) U22.28(GND) U22.34(GND) U22.39(GND) U22.45(GND)
VDD: C79.1 C83.1 R161.1 R166.1 U21.1(DIR) U21.24(DIR) U21.25(~{OE}) U21.31(VCCA) U21.42(VCCA) U22.31(VCCA) U22.42(VCCA)
A0: U21.47(A1)
A0_1DELAY: SB44.1 U21.2(B1) U21.40(A6)
A0_2DELAY: SB45.1 U21.9(B6)
A1: SB51.1 U21.37(A8)
A1_1DELAY: SB50.1 U21.12(B8)
A1_BUF: R166.2 SB50.2 SB51.2 U22.1(DIR) U22.24(DIR)
BL_VDD: C113.2 C115.1 CN19.28(BL_VDD) L4.1 R259.1
D0: U22.26(A8)
D1: U22.27(A7)
D2: U22.29(A6)
D3: U22.30(A5)
D4: U22.32(A4)
D5: U22.33(A3)
D6: U22.35(A2)
D7: U22.36(A1)
D8: U22.37(A8)
D9: U22.38(A7)
D10: U22.40(A6)
D11: U22.41(A5)
D12: U22.43(A4)
D13: U22.44(A3)
D14: U22.46(A2)
D15: U22.47(A1)
LCD_CSN: CN19.1(~{CS}) SB46.2 SB47.2
LCD_D0: CN19.6(PD1) U22.23(B8)
LCD_D1: CN19.7(PD2) U22.22(B7)
LCD_D2: CN19.8(PD3) U22.20(B6)
LCD_D3: CN19.9(PD4) U22.19(B5)
LCD_D4: CN19.10(PD5) U22.17(B4)
LCD_D5: CN19.11(PD6) U22.16(B3)
LCD_D6: CN19.12(PD7) U22.14(B2)
LCD_D7: CN19.13(PD8) U22.13(B1)
LCD_D8: CN19.14(PD10) U22.12(B8)
LCD_D9: CN19.15(PD11) U22.11(B7)
LCD_D10: CN19.16(PD12) U22.9(B6)
LCD_D11: CN19.17(PD13) U22.8(B5)
LCD_D12: CN19.18(PD14) U22.6(B4)
LCD_D13: CN19.19(PD15) U22.5(B3)
LCD_D14: CN19.20(PD16) U22.3(B2)
LCD_D15: CN19.21(PD17) U22.2(B1)
LCD_NE3: SB49.1 U21.46(A2) ; port LCD_NE3
LCD_NE3_BUF: R161.2 SB48.2 SB49.2 U22.25(~{OE}) U22.48(~{OE})
LCD_RDN: CN19.4(~{RD}) U21.6(B4)
LCD_RS: CN19.2(RS) SB44.2 SB45.2
LCD_RSTN: CN19.5(~{RESET}) U21.8(B5)
LCD_WRN: CN19.3(~{WR}/SCL) U21.5(B3)
NE3_1DELAY: SB46.1 SB48.1 U21.3(B2) U21.38(A7)
NE3_2DELAY: SB47.1 U21.11(B7)
PD4: U21.43(A4) ; port FMC_NOE
PD5: U21.44(A3) ; port FMC_NWE
RESET#: U21.41(A5) ; port RESET#
NetC113_1: C113.1 C115.2 CN19.22(BL_GND) L3.1
NetCN19_23: CN19.23(BL_Control) R259.2 T6.3(C)
NetCN19_31: CN19.31(XL) ; port IOExpander_X-
NetCN19_32: CN19.32(XR) ; port IOExpander_X+
NetCN19_33: CN19.33(YD) ; port IOExpander_Y-
NetCN19_34: CN19.34(YU) ; port IOExpander_Y+
NetL4_2: L4.2 R219.2 R223.2
NetR260_1: R260.1 ; port BL_Control
NetR260_2: R260.2 R267.1 T6.1(B)

Not connected (* = marked no-connect by the designer): CN19 29(SDO); U21 13(B1) 14(B2) 16(B3) 17(B4) 19(B5) 20(B6) 22(B7) 23(B8) 26(A8) 27(A7) 29(A6) 30(A5) 32(A4) 33(A3) 35(A2) 36(A1)

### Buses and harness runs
bus A[0..23] = port A[0..23]
bus D[0..15] = port D[0..15]

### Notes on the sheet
- TFT LCD
- 2.8'' LCD TFT board MB989P
- (near U21) PG10
- (near U21) PD5
- (near U21) PF0
- (near U21) PD4

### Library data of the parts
C79 C83-C85 = CAP: as C74 on sheet IDD_measurement
C113 = Cap: as C77 on sheet IDD_measurement
C115 = Cap Pol1: as C107 on sheet Power
CN19 = ColorLCD_module_16bits: Female connector 2x17; Ordered by: Subcon; Comments: LCD TFT paralell; Assembly: with MB989P revB; ECCN_US/EU: NA
L3 L4 = Inductor: as L1 on sheet Power
R161 R166 R267 = res1: as R122 on sheet IDD_measurement
R219 = Res1: as R120 on sheet peripherals
R223 R259 = Res1: as R2-R5 on sheet USB_OTG_FS
R260 = Res1: as R37 on sheet Touch Sensing
SB44 SB46 SB49 SB51 = Circuit Breaker: Ordered by: Subcon; Comments: Solder bridge; Fitted: NO; ECCN_US/EU: NA
SB45 SB47 SB48 SB50 = Circuit Breaker: Ordered by: Subcon; Comments: Solder bridge; ECCN_US/EU: NA
T6 = 9013-SOT23: as T1 on sheet USB_OTG_FS
U21 U22 = SN74LVC16T245: Manuf_1: TI; Ordered by: Subcon; ECCN_US/EU: EAR99/NEC

## Sheet RF_I2C_EEPROM.SchDoc: RF_I2C_EEPROM
size A4; DocumentNumber: 15; Revision: C-02; SheetNumber: 15; SheetTotal: 26; Project: STM32L476G-EVAL
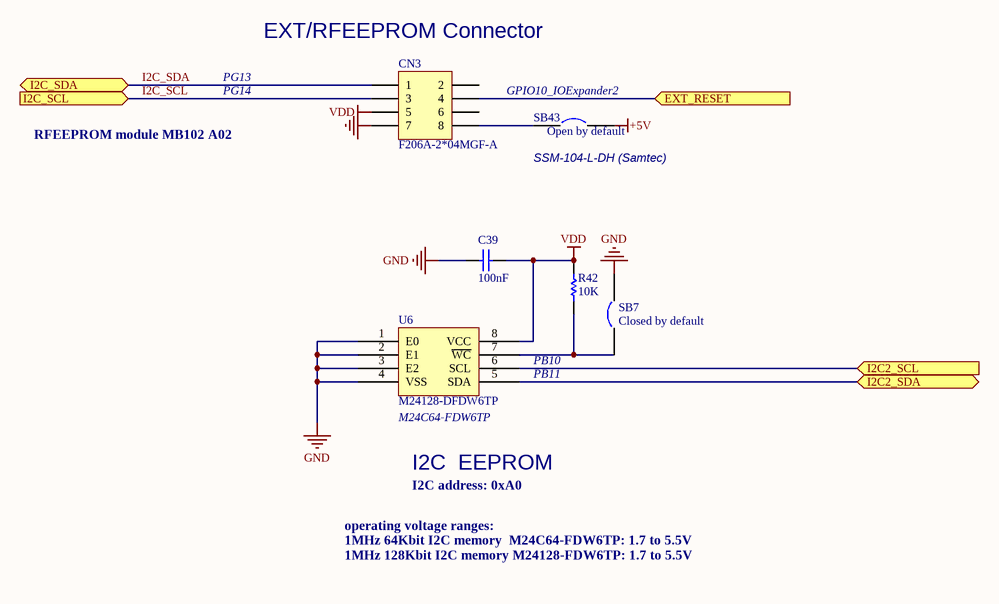
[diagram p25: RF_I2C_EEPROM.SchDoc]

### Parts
C39  100nF  [0402C]
CN3  F206A-2*04MGF-A  [SSM-104-L-DH]
R42  10K  [0402R]
SB7  Closed by default  [SB_0603]
SB43  Open by default  [SB_0603]
U6  M24128-DFDW6TP  [TSSOP8_0R65_3X6R4]

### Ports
EXT_RESET (in), I2C2_SCL (in), I2C2_SDA (bidir), I2C_SCL (in), I2C_SDA (bidir)

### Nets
+5V: SB43.2
GND: C39.1 CN3.7 SB7.2 U6.1(E0) U6.2(E1) U6.3(E2) U6.4(VSS)
VDD: C39.2 CN3.5 R42.1 U6.8(VCC)
I2C_SCL: CN3.3 ; port I2C_SCL
I2C_SDA: CN3.1 ; port I2C_SDA
NetCN3_4: CN3.4 ; port EXT_RESET
NetCN3_8: CN3.8 SB43.1
NetR42_2: R42.2 SB7.1 U6.7(~{WC})
NetR263_2: U6.5(SDA) ; port I2C2_SDA
NetR264_2: U6.6(SCL) ; port I2C2_SCL

Not connected (* = marked no-connect by the designer): CN3 2 6

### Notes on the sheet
- PG13
- (near CN3) EXT/RFEEPROM Connector
- RFEEPROM module MB102 A02
  I2C address: 0xA6
- PG14
- (near SB43) GPIO10_IOExpander2
- SSM-104-L-DH (Samtec)
- PB11
- PB10
- (near U6) M24C64-FDW6TP
- I2C  EEPROM
- I2C address: 0xA0
- operating voltage ranges:
  1MHz 64Kbit I2C memory  M24C64-FDW6TP: 1.7 to 5.5V
  1MHz 128Kbit I2C memory M24128-FDW6TP: 1.7 to 5.5V

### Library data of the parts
C39 = CAP: as C74 on sheet IDD_measurement
CN3 = SSM-104-L-DH: Header, 5-Pin, Dual row; Ordered by: Subcon; Comments: EXT/RF E2P connector; ECCN_US/EU: NA; Assembly: with MB1020 A02
R42 = Res1: as R2-R5 on sheet USB_OTG_FS
SB7 = Circuit Breaker: as SB45 on sheet LCD_TFT
SB43 = Circuit Breaker: as SB44 on sheet LCD_TFT
U6 = M24C64-WMN6: Ordered by: ST; ECCN_US/EU: EAR99/NEC; Ref St: 9175653

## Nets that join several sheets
+1V8: Power (C107.1 TP16.1 U27.2 U27.4), Audio (6 pins)
+3V3: MotorControl (CN2.28 R14.2 R20.2), Extension connector (R44.1), USART_IrDA (10 pins), SWP_SmartCard_NFC (9 pins), USB_OTG_FS (R6.1 R8.1 R9.1), CAN (R70.1), peripherals (LD1.1 LD2.1 LD3.1 LD4.1), Power (9 pins), Audio (5 pins), LCD_TFT (9 pins)
+3V6: SRAM&Flash (C20.1 U5.G5), Power (5 pins)
+5V: MotorControl (CN2.25), ST_LINK (R169.2), SWP_SmartCard_NFC (C135.1 C138.1 U30.6), IDD_measurement (C75.1 R128.1 U15.4), USB_OTG_FS (U1.5), Power (11 pins), LCD_TFT (R223.1), RF_I2C_EEPROM (SB43.2)
D5V: Extension connector (CN6.28), ST_LINK (D7.1), Power (JP17.2)
E5V: ST_LINK (D5.1), Power (C100.1 JP17.8 L2.2)
GND: MCU (R100.2 R101.2 R102.2), LCD_Glass (R138.2 R139.2), IO_Expandor (10 pins), MCU2 (9 pins), SRAM&Flash (13 pins), MotorControl (26 pins), MicroSD (C90.2 CN18.6 CN18.9), QSPI (C44.2 U9.4), Extension connector (9 pins), JTAG&Trace (24 pins), ST_LINK (38 pins), USART_IrDA (19 pins), SWP_SmartCard_NFC (17 pins), STPMS2&PT100 (20 pins), IDD_measurement (12 pins), USB_OTG_FS (12 pins), Touch Sensing (C34.1 C37.1), CAN (10 pins), peripherals (9 pins), Power (60 pins), Audio (40 pins), LCD_TFT (27 pins), RF_I2C_EEPROM (7 pins)
U5V: ST_LINK (D6.1), USB_OTG_FS (R2.1), Power (JP17.6)
U5V_STLINK: ST_LINK (C143.2 U37.6 U37.7), Power (JP17.4)
VDD: LCD_Glass (R263.1 R264.1), IO_Expandor (9 pins), MCU2 (R57.2 R60.2 R96.2 SW1.1), SRAM&Flash (16 pins), MicroSD (7 pins), QSPI (C44.1 R74.1 U9.8), Extension connector (CN7.40), JTAG&Trace (8 pins), ST_LINK (8 pins), USART_IrDA (5 pins), SWP_SmartCard_NFC (C112.1 C119.1 U30.21), STPMS2&PT100 (5 pins), IDD_measurement (11 pins), CAN (C49.2 R46.2 U8.3), peripherals (10 pins), Power (JP2.2 JP12.1 TP5.1), Audio (6 pins), LCD_TFT (11 pins), RF_I2C_EEPROM (C39.2 CN3.5 R42.1 U6.8)
VDD_MCU: IDD_measurement (JP11.2 JP11.3), Power (21 pins)
VDDA: peripherals (CN10.2), Power (5 pins)
A0: MCU2 (U7.10), Extension connector (CN6.25)
A0: SRAM&Flash (U2.A3 U5.E2), LCD_TFT (U21.47)
A1: MCU2 (U7.11), Extension connector (CN6.26)
A1: SRAM&Flash (U2.A4 U5.D2), LCD_TFT (SB51.1 U21.37)
A2: MCU2 (U7.12), Extension connector (CN6.32)
A3: MCU2 (U7.13), Extension connector (CN6.34)
A4: MCU2 (U7.14), Extension connector (CN6.37)
A5: MCU2 (U7.15), Extension connector (CN6.38)
A6: MCU2 (U7.50), Extension connector (CN7.17)
A7: MCU2 (U7.53), Extension connector (CN7.18)
A8: MCU2 (U7.54), Extension connector (CN7.16)
A9: MCU2 (U7.55), Extension connector (CN7.14)
A10: MCU2 (U7.56), Extension connector (CN7.12)
A11: MCU2 (U7.57), Extension connector (CN7.11)
A12: MCU2 (U7.87), Extension connector (CN6.13)
A13: MCU2 (U7.88), Extension connector (CN6.12)
A14: MCU2 (U7.89), Extension connector (CN6.14)
A15: MCU2 (U7.90), Extension connector (CN6.10)
BOOT0: MCU2 (JP8.1 R67.1 U7.138), Extension connector (CN7.20)
Comp2_INP: LCD_Glass (CN11.44), peripherals (JP7.3)
Comp2_OUT: LCD_Glass (CN11.14), peripherals (TP6.1)
D0: LCD_Glass (CN14.36), SRAM&Flash (U2.B6 U5.E3), LCD_TFT (U22.26)
D1: LCD_Glass (CN14.38), SRAM&Flash (U2.C5 U5.H3), LCD_TFT (U22.27)
D2: MCU (U7.114), SRAM&Flash (U2.C6 U5.E4), Extension connector (CN6.17), LCD_TFT (U22.29)
D3: MCU (U7.115), SRAM&Flash (U2.D5 U5.H4), Extension connector (CN6.16), LCD_TFT (U22.30)
D4: MCU (U7.58), SRAM&Flash (U2.E5 U5.H5), Extension connector (CN7.10), LCD_TFT (U22.32)
D5: MCU (U7.59), SRAM&Flash (U2.F5 U5.E5), Extension connector (CN7.9), LCD_TFT (U22.33)
D6: MCU (U7.60), SRAM&Flash (U2.F6 U5.H6), Extension connector (CN7.8), LCD_TFT (U22.35)
D7: MCU (U7.63), SRAM&Flash (U2.G6 U5.E6), Extension connector (CN7.7), LCD_TFT (U22.36)
D8: MCU (U7.64), SRAM&Flash (U2.B1 U5.F3), Extension connector (CN7.6), LCD_TFT (U22.37)
D9: MCU (U7.65), SRAM&Flash (U2.C1 U5.G3), Extension connector (CN7.5), LCD_TFT (U22.38)
D10: MCU (U7.66), SRAM&Flash (U2.C2 U5.F4), Extension connector (CN7.4), LCD_TFT (U22.40)
D11: MCU (U7.67), SRAM&Flash (U2.D2 U5.G4), Extension connector (CN7.3), LCD_TFT (U22.41)
D12: MCU (U7.68), SRAM&Flash (U2.E2 U5.F5), Extension connector (CN7.2), LCD_TFT (U22.43)
D13: LCD_Glass (CN14.24), SRAM&Flash (U2.F2 U5.G6), LCD_TFT (U22.44)
D14: LCD_Glass (CN14.26), SRAM&Flash (U2.F1 U5.F6), LCD_TFT (U22.46)
D15: LCD_Glass (CN14.28), SRAM&Flash (U2.G1 U5.G7), LCD_TFT (U22.47)
I2C_SCL: IO_Expandor (U32.4 U33.19), MCU2 (R60.1 R61.1), Audio (U29.H1), RF_I2C_EEPROM (CN3.3)
I2C_SDA: IO_Expandor (U32.5 U33.20), MCU2 (R57.1 R58.1), Audio (U29.F3), RF_I2C_EEPROM (CN3.1)
LCD_NE3: MCU2 (U7.125), Extension connector (CN6.21), LCD_TFT (SB49.1 U21.46)
LCDSEG7: MCU (U7.133), JTAG&Trace (RS1.9), ST_LINK (U24.6)
LCDSEG8: MCU (U7.134), JTAG&Trace (RS1.5), ST_LINK (U23.19)
LCDSEG17: MCU (U7.110), JTAG&Trace (RS1.7), ST_LINK (U23.17)
NetB3_1: IO_Expandor (U33.3), peripherals (B3.1 R248.1)
NetB3_2: IO_Expandor (U33.1), peripherals (B3.2 R246.2)
NetB3_3: IO_Expandor (U33.2), peripherals (B3.3 R247.1)
NetB3_4: IO_Expandor (U33.4), peripherals (B3.4 R249.1)
NetB3_6: IO_Expandor (U33.5), peripherals (B3.6 R250.1)
NetC1_2: MCU (SB32.1), MotorControl (C1.2 CN2.33)
NetC2_2: MCU (SB31.1), MotorControl (C2.2 CN2.34)
NetC3_1: MCU2 (SB17.1), MotorControl (C3.1 R7.2)
NetC4_2: MCU (SB35.1), MotorControl (C4.2 CN2.31 SB1.2)
NetC5_2: MCU (SB3.1), MotorControl (C5.2 CN2.30 R20.1)
NetC6_2: MCU (SB20.1), MotorControl (C6.2 R12.2)
NetC7_2: MCU2 (SB29.1), MotorControl (C7.2 CN2.1 R14.1)
NetC9_2: MCU2 (SB37.2), MotorControl (C9.2 CN2.29)
NetC10_2: MCU2 (SB42.1), MotorControl (C10.2 R17.1)
NetC11_1: MCU2 (SB16.1), MotorControl (C11.1 R13.2 R19.1)
NetC13_2: MCU2 (SB36.1), MotorControl (C13.2 R10.1)
NetC14_2: MCU2 (SB34.1), MotorControl (C14.2 R11.1)
NetC15_1: LCD_Glass (CN11.2 R108.2), USB_OTG_FS (6 pins)
NetC16_2: MCU2 (SB25.2), MotorControl (C16.2 R15.1)
NetC17_1: MCU (SB22.1), MotorControl (C17.1 R16.2)
NetC34_2: MCU2 (SB4.1), Touch Sensing (C34.2)
NetC37_2: MCU (SB6.1), Touch Sensing (C37.2)
NetC52_2: peripherals (C52.2 C53.1 R92.2), Power (U7.32)
NetC73_1: MCU (R69.2), IDD_measurement (C73.1 R122.2)
NetCN2_3: MCU2 (SB27.1), MotorControl (CN2.3)
NetCN2_5: MCU (SB19.1), MotorControl (CN2.5)
NetCN2_7: MCU2 (SB30.1), MotorControl (CN2.7)
NetCN2_9: MCU (SB15.1), MotorControl (CN2.9)
NetCN2_11: MCU2 (SB28.1), MotorControl (CN2.11)
NetCN2_13: MCU (SB13.1), MotorControl (CN2.13)
NetCN2_21: MCU2 (SB5.2), MotorControl (CN2.21)
NetCN2_23: MCU (SB11.1), MotorControl (CN2.23)
NetCN3_4: IO_Expandor (U33.12), RF_I2C_EEPROM (CN3.4)
NetCN11_4: LCD_Glass (CN11.4), MicroSD (R194.1)
NetCN11_6: LCD_Glass (CN11.6), USB_OTG_FS (R5.2)
NetCN11_8: LCD_Glass (CN11.8), CAN (R75.2)
NetCN11_16: LCD_Glass (CN11.16), SWP_SmartCard_NFC (CN13.4)
NetCN11_18: LCD_Glass (CN11.18 R108.1), SWP_SmartCard_NFC (CN13.6)
NetCN11_20: LCD_Glass (CN11.20 R109.1), SWP_SmartCard_NFC (CN23.6)
NetCN11_24: LCD_Glass (CN11.24), CAN (R76.1)
NetCN11_26: LCD_Glass (CN11.26), SWP_SmartCard_NFC (CN13.5)
NetCN11_28: LCD_Glass (CN11.28), STPMS2&PT100 (6 pins), Audio (JP14.3)
NetCN11_30: LCD_Glass (CN11.30), peripherals (R256.1)
NetCN11_32: LCD_Glass (CN11.32), Audio (U29.A9 U35.4 U36.4)
NetCN12_12: MCU (SB26.2), JTAG&Trace (CN12.12 U18.4)
NetCN12_18: MCU (SB38.2), JTAG&Trace (CN12.18 U19.3)
NetCN12_20: MCU (SB39.2), JTAG&Trace (CN12.20 U19.1)
NetCN13_1: USART_IrDA (JP15.6), SWP_SmartCard_NFC (CN13.1)
NetCN13_2: USART_IrDA (U10.13 U11.3 U12.7), SWP_SmartCard_NFC (CN13.2)
NetCN14_2: LCD_Glass (CN14.2), MicroSD (CN18.3 R178.2)
NetCN14_10: LCD_Glass (CN14.10), USART_IrDA (JP15.1 JP15.3 JP15.5 R158.1)
NetCN14_40: LCD_Glass (CN14.40), SRAM&Flash (U2.A1)
NetCN14_42: LCD_Glass (CN14.42), SRAM&Flash (U2.B2)
NetCN18_1: LCD_Glass (R142.1), MicroSD (CN18.1 R175.2)
NetCN18_2: LCD_Glass (R141.1), MicroSD (CN18.2 R176.2)
NetCN18_5: LCD_Glass (R140.1), MicroSD (CN18.5)
NetCN18_7: LCD_Glass (R147.1), MicroSD (CN18.7 R182.2)
NetCN18_8: LCD_Glass (R148.1), MicroSD (CN18.8 R185.2)
NetCN19_31: IO_Expandor (U32.16), LCD_TFT (CN19.31)
NetCN19_32: IO_Expandor (U32.13), LCD_TFT (CN19.32)
NetCN19_33: IO_Expandor (U32.1), LCD_TFT (CN19.33)
NetCN19_34: IO_Expandor (U32.15), LCD_TFT (CN19.34)
NetD4_2: MCU2 (D4.2), USART_IrDA (R93.1 U10.16)
NetJP19_1: LCD_Glass (R145.1), USB_OTG_FS (JP19.1)
NetLD6_2: LCD_Glass (R109.2), USB_OTG_FS (LD6.2 R8.2 U1.3)
NetR24_1: LCD_Glass (R146.1), STPMS2&PT100 (R24.1)
NetR32_2: MCU (SB10.2), SRAM&Flash (R32.2 U5.A4)
NetR34_1: MCU2 (R34.1), ST_LINK (R189.1), USART_IrDA (R119.2)
NetR35_1: MCU2 (R35.1), Audio (R199.2)
NetR37_1: MCU2 (SB2.1), Touch Sensing (R37.1)
NetR39_1: MCU (R39.1 SB3.2 U7.73), Touch Sensing (R40.1)
NetR53_2: MCU (R53.2), Audio (R205.2)
NetR54_2: MCU (R54.2), peripherals (R258.1)
NetR59_2: MCU2 (R59.2), USART_IrDA (U10.20)
NetR71_2: MCU (SB8.1), QSPI (R71.2)
NetR89_1: MCU2 (R89.1), Audio (R201.2)
NetR90_1: MCU2 (R90.1), Audio (R208.2)
NetR91_1: MCU2 (R91.1), IDD_measurement (R127.2 U14.12)
NetR104_1: MCU (R104.1 U7.2), JTAG&Trace (R154.2)
NetR105_1: MCU2 (R105.1), Audio (R198.2)
NetR106_1: MCU2 (R106.1), Audio (R222.1)
NetR107_1: LCD_Glass (R107.1), SWP_SmartCard_NFC (U30.24)
NetR137_1: LCD_Glass (R144.1), IDD_measurement (5 pins)
NetR143_1: LCD_Glass (R143.1), SWP_SmartCard_NFC (R210.2)
NetR156_2: MCU (SB40.2), JTAG&Trace (R156.2)
NetR213_1: IO_Expandor (U33.10), SWP_SmartCard_NFC (R213.1 U30.23)
NetR214_2: IO_Expandor (U33.6), SWP_SmartCard_NFC (R214.2 U30.20)
NetR215_2: IO_Expandor (U33.7), SWP_SmartCard_NFC (R215.2 U30.19)
NetR241_1: IO_Expandor (U33.8), SWP_SmartCard_NFC (R241.1 U30.3)
NetR255_1: IO_Expandor (U32.11), peripherals (R255.1)
NetR257_1: IO_Expandor (U32.8), peripherals (R257.1)
NetR260_1: IO_Expandor (U33.11), LCD_TFT (R260.1)
NetR263_2: LCD_Glass (R263.2 R265.1), RF_I2C_EEPROM (U6.5)
NetR264_2: LCD_Glass (R264.2 R266.1), RF_I2C_EEPROM (U6.6)
NetSB9_1: MCU (SB9.1), QSPI (U9.6)
NetSB12_1: MCU (SB12.1), QSPI (U9.5)
NetSB14_1: MCU (SB14.1), QSPI (U9.2)
NetSB18_1: MCU (SB18.1), QSPI (U9.3)
NetSB21_1: MCU (SB21.1), QSPI (U9.7)
OpAmp1_INM: LCD_Glass (CN14.48), peripherals (R120.1 R121.2 RV2.1)
OpAmp1_INP: MCU (R83.2), peripherals (R63.2)
OpAmp1_OUT: LCD_Glass (R111.1), peripherals (RV2.2 RV2.3 TP9.1)
PA0: MCU (R83.1 SB35.2 U7.34), Extension connector (CN7.37)
PA4: MCU (U7.40), Extension connector (CN7.38), peripherals (R73.1)
PA5: MCU (R69.1 U7.41), Extension connector (CN7.35)
PA11: MCU (U7.103), Extension connector (CN6.6), USB_OTG_FS (D1.D3 R3.2)
PA12: MCU (U7.104), Extension connector (CN6.7), USB_OTG_FS (D1.C3 R4.2)
PA13: MCU (U7.105), Extension connector (CN6.5), JTAG&Trace (RS1.13), ST_LINK (U23.27 U24.7)
PA14: MCU (U7.109), Extension connector (CN6.8), JTAG&Trace (RS1.11), ST_LINK (U23.15 U23.26)
PB2: MCU (R54.1 SB11.2 U7.48), Extension connector (CN7.13)
PB6: MCU (U7.136), Extension connector (CN6.40), USART_IrDA (R118.2)
PC3: MCU2 (R94.1 U7.29), Extension connector (CN7.36)
PC13: MCU2 (U7.7), Extension connector (R80.2), peripherals (R244.2)
PC14: MCU2 (R87.2 U7.8), Extension connector (SB41.1)
PC15: MCU2 (R88.2 U7.9), Extension connector (SB33.1)
PD3: MCU (U7.117), Extension connector (CN6.15), STPMS2&PT100 (R23.1)
PD4: MCU (U7.118), SRAM&Flash (U2.A2 U5.G2), Extension connector (CN6.18), LCD_TFT (U21.43)
PD5: MCU (U7.119), SRAM&Flash (U2.G5 U5.A5), Extension connector (CN6.19), LCD_TFT (U21.44)
PD6: MCU (R53.1 SB10.1 U7.122), Extension connector (CN6.24)
PD7: MCU (U7.123), SRAM&Flash (R18.2), Extension connector (CN6.23)
PE4: MCU (R84.2 SB40.1 U7.3), Extension connector (CN7.21)
PE5: MCU (R85.2 SB38.1 U7.4), Extension connector (CN7.23)
PE6: MCU (R86.2 SB39.1 U7.5), Extension connector (CN7.22)
PF6: MCU2 (R105.2 U7.18), Extension connector (CN7.27)
PF7: MCU2 (R106.2 U7.19), Extension connector (CN7.28)
PF8: MCU2 (R89.2 U7.20), Extension connector (CN7.30)
PF9: MCU2 (R90.2 SB25.1 U7.21), Extension connector (CN7.29)
PF10: MCU2 (R91.2 SB37.1 U7.22), Extension connector (CN7.31)
PF11: MCU2 (U7.49), Extension connector (CN7.19), SWP_SmartCard_NFC (CN13.3)
PG6: MCU2 (R35.2 SB5.1 U7.91), Extension connector (CN6.3)
PG7: MCU2 (R34.2 U7.92), Extension connector (CN6.4)
PG8: MCU2 (U7.93), Extension connector (CN6.9), ST_LINK (R188.2), USART_IrDA (R158.2)
PG9: MCU2 (U7.124), SRAM&Flash (R43.2), Extension connector (CN6.20)
PG11: MCU2 (U7.126), Extension connector (CN6.27), USART_IrDA (R93.2)
PG12: MCU2 (U7.127), Extension connector (CN6.31), USART_IrDA (R116.2)
PG13: MCU2 (R58.2 U7.128), Extension connector (CN6.29)
PG14: MCU2 (R61.2 U7.129), Extension connector (CN6.33)
PG15: IO_Expandor (R228.1), MCU2 (U7.132), Extension connector (CN6.35)
PH0: MCU2 (C54.1 U7.23 X2.2), Extension connector (SB24.1)
PH1: MCU2 (R95.1 U7.24), Extension connector (SB23.1)
RESET#: MCU2 (6 pins), Extension connector (R79.1), JTAG&Trace (RS1.3), ST_LINK (U23.18), LCD_TFT (U21.41)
